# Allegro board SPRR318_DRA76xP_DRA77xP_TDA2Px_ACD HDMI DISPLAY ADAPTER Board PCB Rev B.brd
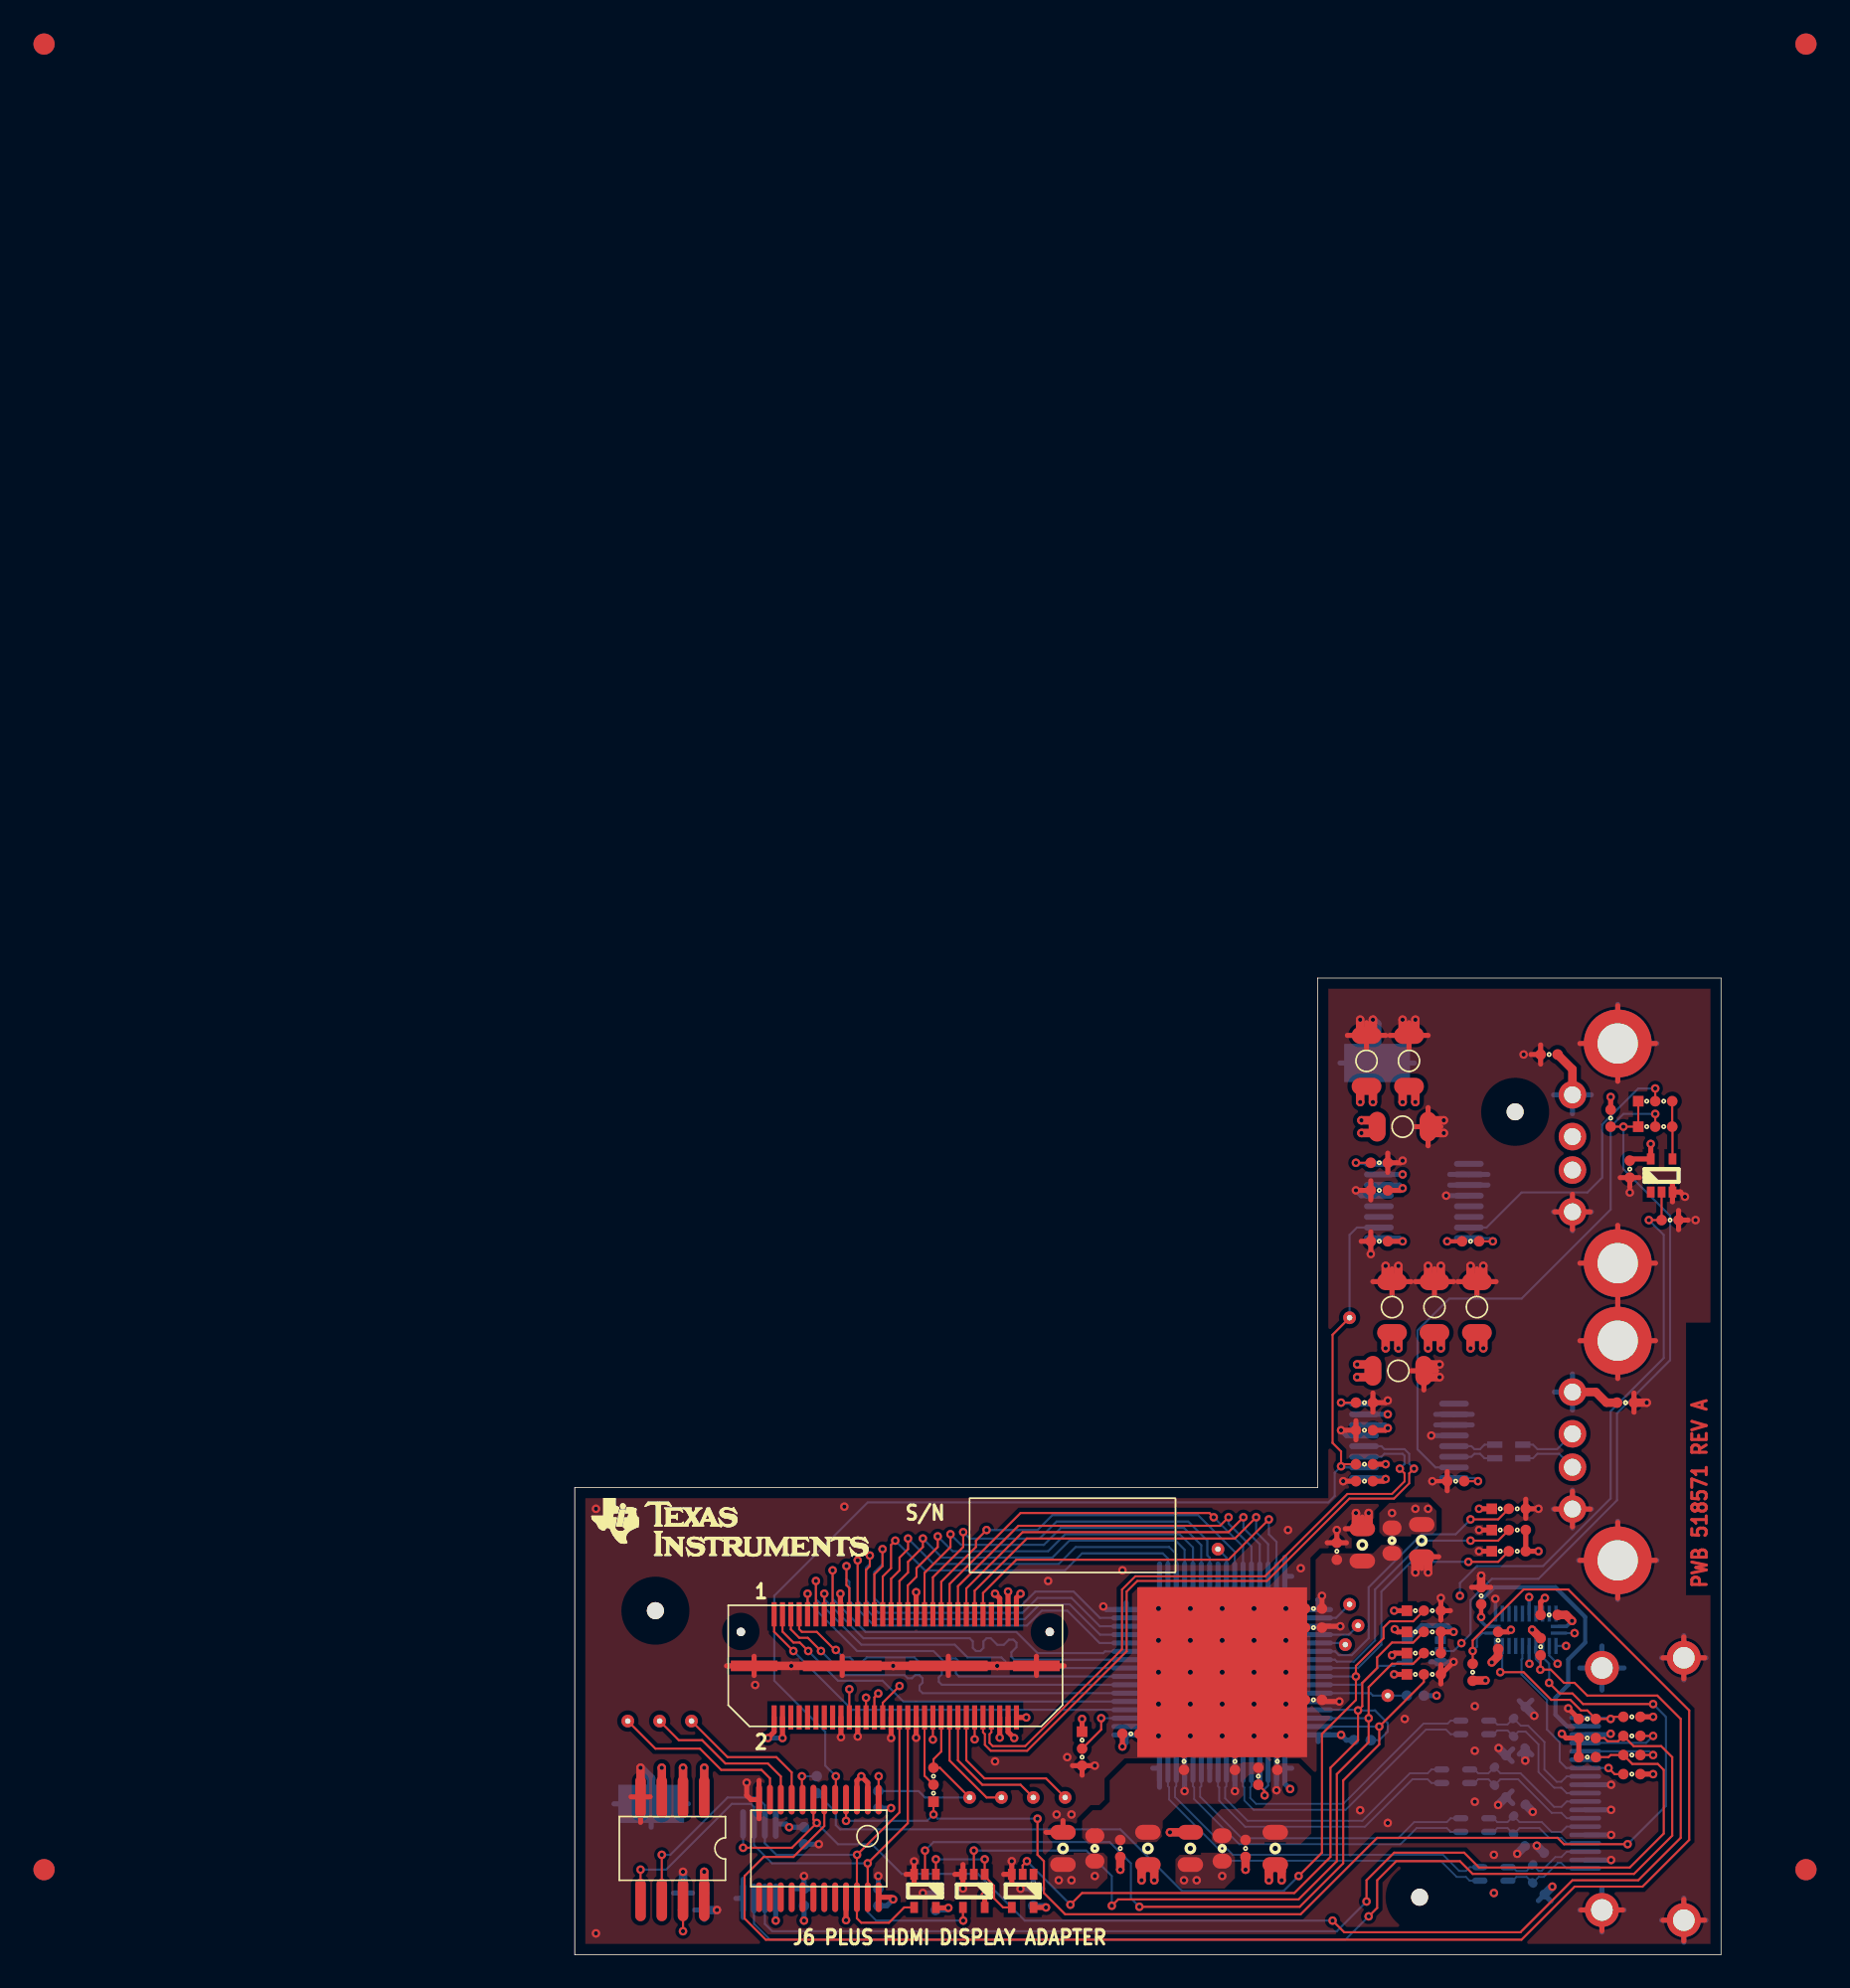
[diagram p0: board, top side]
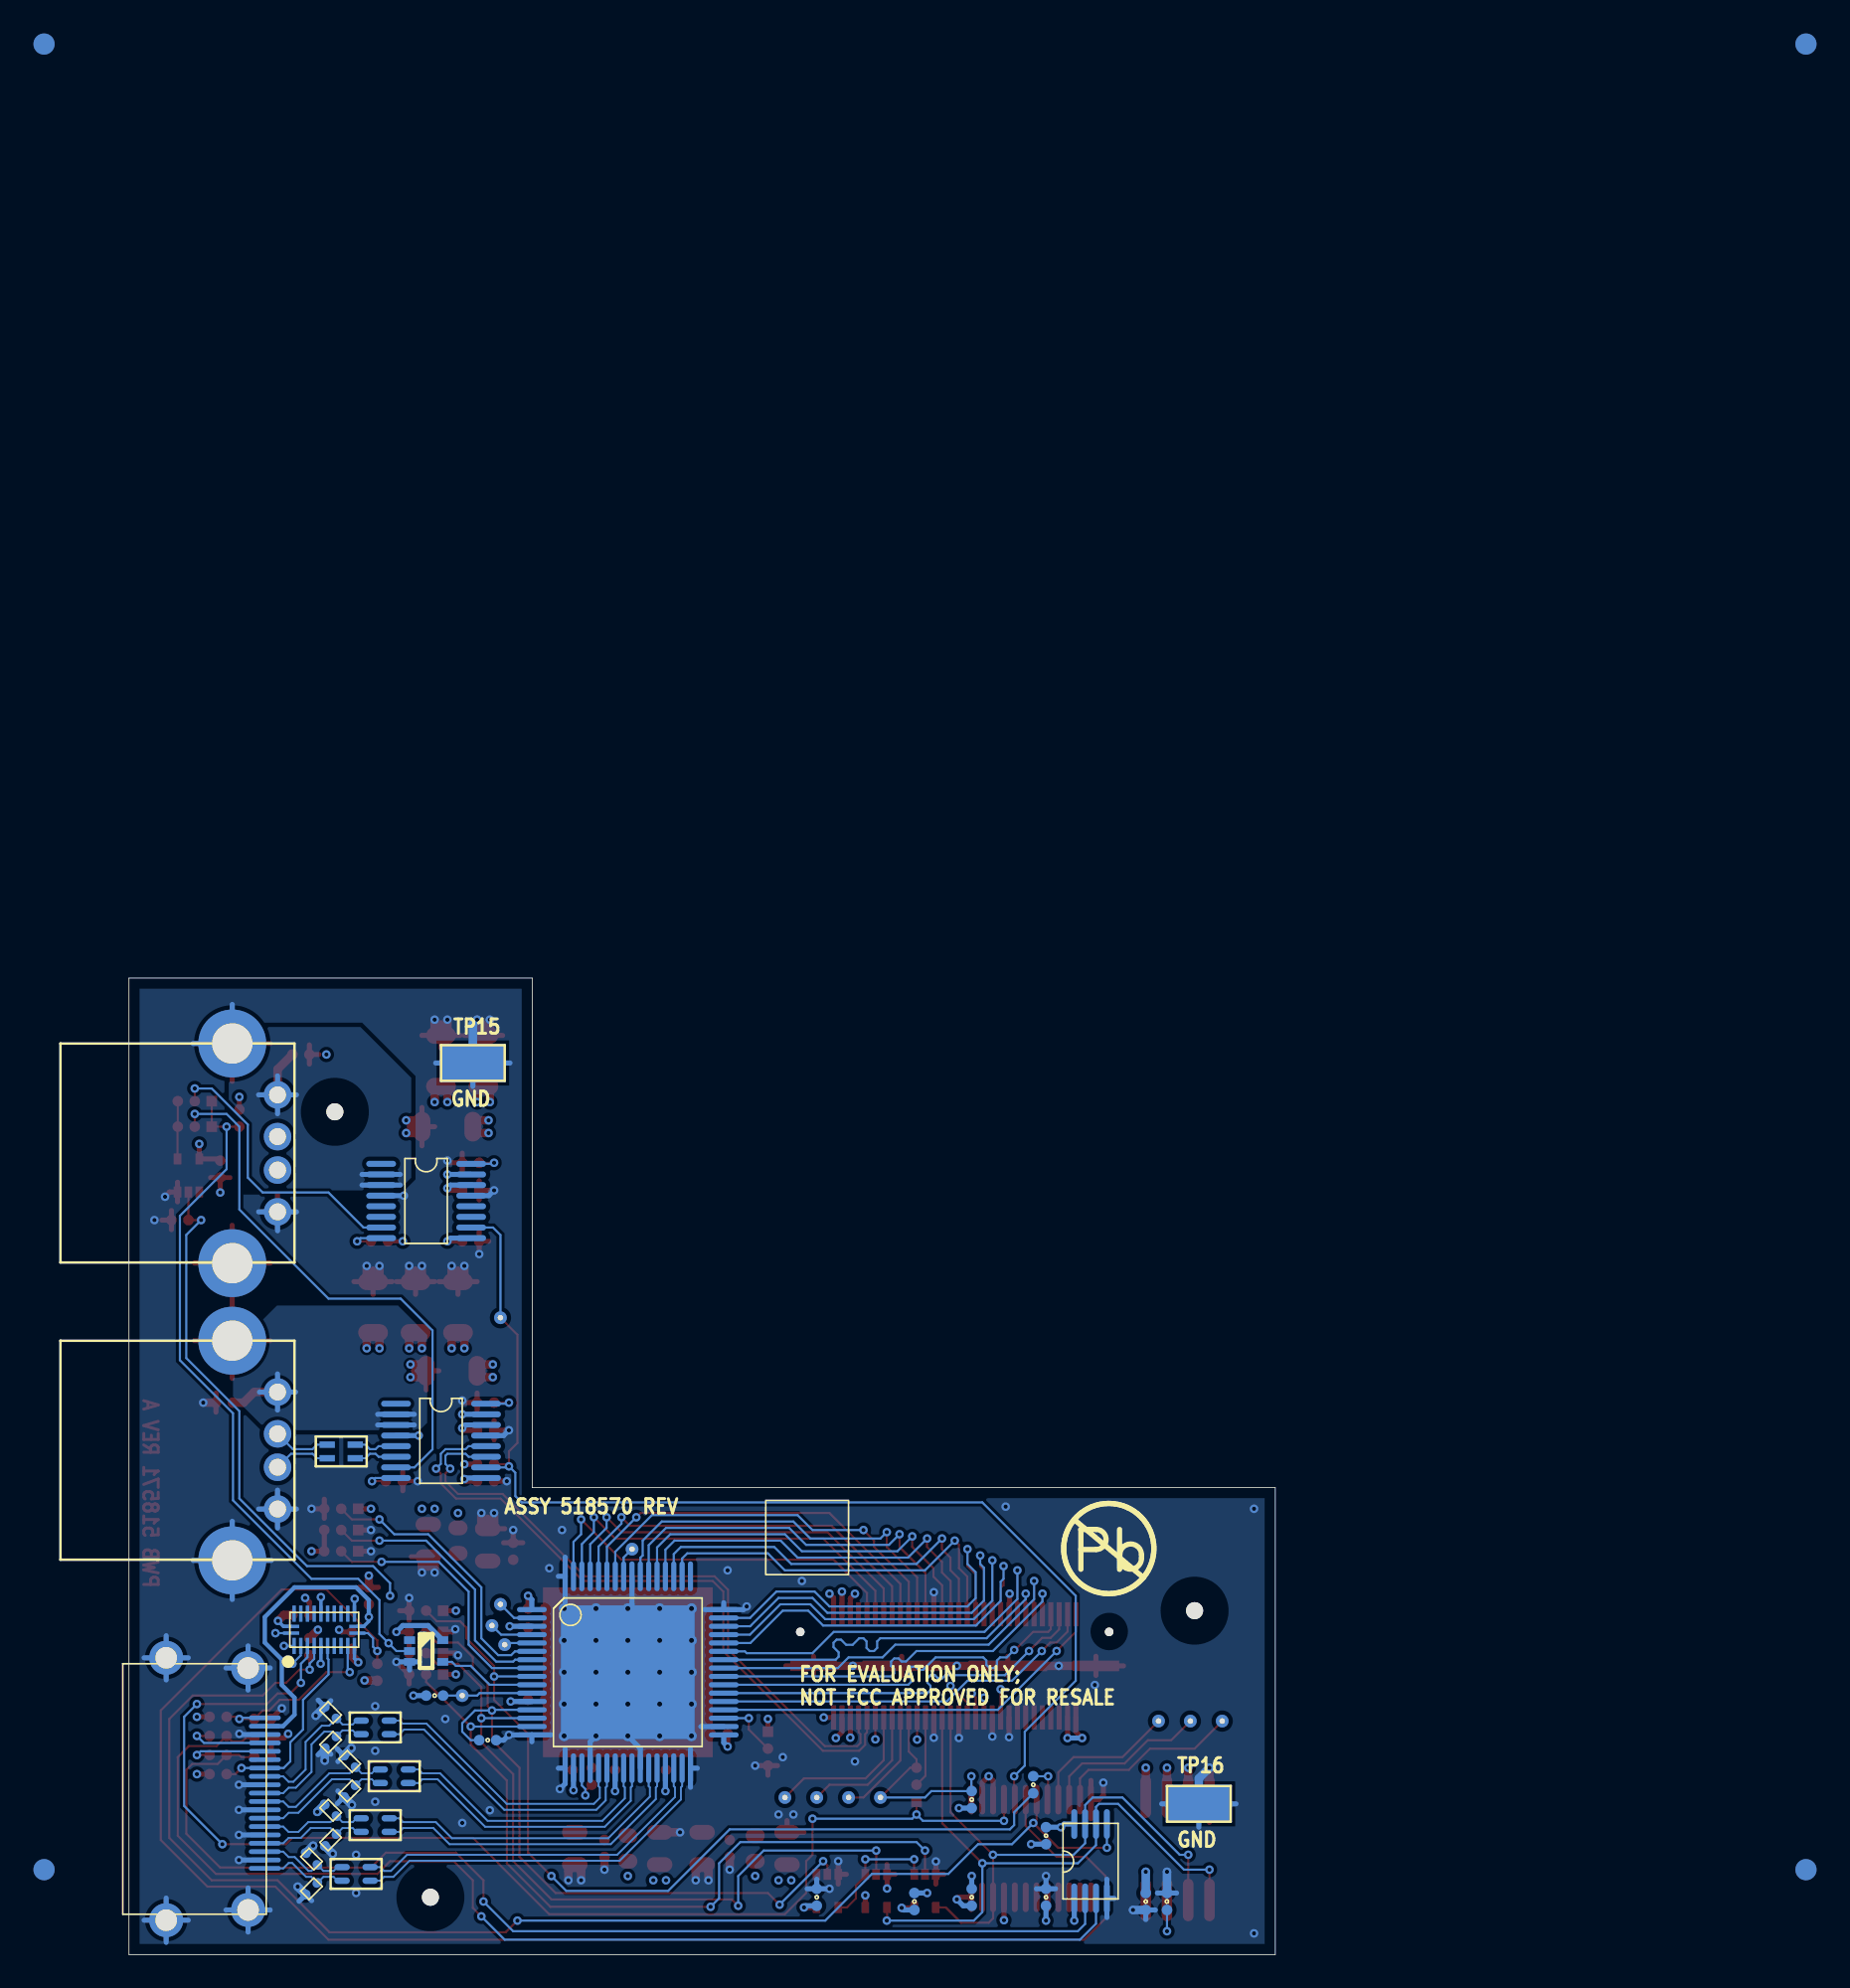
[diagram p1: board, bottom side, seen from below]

Outline 68.58 x 58.42 mm; copper layers: TOP, L2-GND1, L3-SIGNAL, L4-SIGNAL, L5-GND2, BOTTOM. Coordinates in mm from the lower left corner of the outline.
Outline path: 0,27.94 0,0 68.58,0 68.58,58.42 44.45,58.42 44.45,27.94 0,27.94

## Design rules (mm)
net group DP_CON_USB2: nets CONN_USB2_DM CONN_USB2_DP
net group HDMI_CK+: nets HDMI_CK+ TXC+
net group HDMI_CK-: nets HDMI_CK- TXC-
net group HDMI_D0+: nets HDMI_D0+ TX0+
net group HDMI_D0-: nets HDMI_D0- TX0-
net group HDMI_D1+: nets HDMI_D1+ TX1+
net group HDMI_D1-: nets HDMI_D1- TX1-
net group HDMI_D2+: nets HDMI_D2+ TX2+
net group HDMI_D2-: nets HDMI_D2- TX2-
net group 90-OHM: nets USB2_VD+ USB2_VD- USB_DM_DN2 USB_DP_DN2
net group LCD: nets LCD_B0 LCD_B1 LCD_B2 LCD_B3 LCD_B4 LCD_B5 LCD_B6 LCD_B7 LCD_G0 LCD_G1 LCD_G2 LCD_G3 LCD_G4 LCD_G5 LCD_G6 LCD_G7 LCD_R0 LCD_R1 LCD_R2 LCD_R3 LCD_R4 LCD_R5 LCD_R6 LCD_R7
net group PWR: nets VIO_1V8
net group SYNC: nets LCD_DE LCD_HS LCD_PCLK LCD_VS

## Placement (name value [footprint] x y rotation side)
C1  10uF  [C1206-40X70]  47.37 53.47 90 top
C2  10uF  [C1206-40X70]  49.91 53.47 90 top
C3  0.1uF  [C402-25]  58.29 53.85 180 top
C4  10uF  [C1206-40X70]  49.53 49.53 0 top
C5  0.1uF  [C402-25]  48.13 45.72 180 top
C6  1uF  [C402-25]  48.13 42.67 180 top
C7  10uF  [C1206-40X70]  48.9 38.73 90 top
C8  10uF  [C1206-40X70]  51.44 38.73 90 top
C9  10uF  [C1206-40X70]  53.98 38.73 90 top
C10  10uF  [C1206-40X70]  49.28 34.92 0 top
C11  0.1uF  [C402-25]  62.87 33.02 0 top
C12  0.1uF  [C402-25]  47.24 31.37 180 top
C13  1uF  [C402-25]  47.24 28.32 180 top
C14  10uF  [C805-35X60]  50.67 24.77 270 top
C15  0.1uF  [C402-25]  45.59 24.13 90 top
C16  10uF  [C805-35X60]  47.12 24.51 90 top
C17  0.01uF  [C402-25]  44.2 20.7 180 top
C18  0.01uF  [C402-25]  44.2 19.56 180 top
C19  0.1uF  [C402-25]  44.2 15.24 180 top
C20  0.1uF  [C402-25]  33.27 13.21 0 top
C21  0.1uF  [C402-25]  36.45 11.56 90 top
C22  0.01uF  [C402-25]  39.5 11.56 90 top
C23  0.01uF  [C402-25]  42.04 11.56 90 top
C24  0.1uF  [C402-25]  32.64 6.35 270 top
C25  0.1uF  [C402-25]  40.13 6.35 270 top
C26  10uF  [C805-35X60]  34.29 6.35 270 top
C27  10uF  [C805-35X60]  41.91 6.35 270 top
C28  10uF  [C805-35X60]  29.21 6.35 90 top
C29  10uF  [C805-35X60]  36.83 6.35 90 top
C30  0.1uF  [C402-25]  27.43 3.43 90 bottom
C31  0.1uF  [C402-25]  54.23 21.46 90 top
C32  0.1uF  [C402-25]  55.24 18.8 90 top
C33  0.1uF  [C402-25]  21.59 3.17 90 bottom
C34  0.1uF  [C402-25]  7.75 3.17 90 bottom
C35  0.1uF  [C402-25]  58.29 20.32 180 top
C36  0.1uF  [C402-25]  18.16 3.43 90 bottom
C37  NP-1uF  [C402-25]  47.12 12.83 180 bottom
C38  0.1uF  [C402-25]  63.12 46.99 90 top
C39  0.1uF  [C402-25]  13.72 7.11 270 bottom
C40  0.1uF  [C402-25]  13.72 3.43 90 bottom
FL1  DLW21SN121HQ2  [EMI-36X15-DLW21]  55.88 30.1 0 bottom
FL2  DLW21SN900HQ2  [EMI-36X15-DLW21-RDPADS]  54.99 4.83 0 bottom
FL3  DLW21SN900HQ2  [EMI-36X15-DLW21-RDPADS]  53.85 7.75 0 bottom
FL4  DLW21SN900HQ2  [EMI-36X15-DLW21-RDPADS]  52.7 10.67 0 bottom
FL5  DLW21SN900HQ2  [EMI-36X15-DLW21-RDPADS]  53.85 13.59 0 bottom
J1  QTH-030-02-L-D-A  [QTH30-12X57]  19.18 17.27 0 top
L1  BLM18AG601SN1D  [L603-35X45]  48.9 24.77 270 top
L2  BLM18AG601SN1D  [L603-35X45]  38.73 6.35 90 top
L3  BLM18AG601SN1D  [L603-35X45]  31.11 6.35 90 top
NOREF  -  []  0.13 23.62 0 top
NOREF#2  -  []  -36.83 119.38 0 top
NOREF#3  -  []  68.58 0 0 top
NOREF#4  -  [unnamed#2]  73.66 5.08 0 top
NOREF#5  -  []  68.58 117.43 0 top
NOREF#6  -  [unnamed#2]  -31.75 5.08 0 top
NOREF#7  -  [unnamed#2]  73.66 114.3 0 top
NOREF#8  -  []  68.58 0 90 top
NOREF#9  -  []  78.74 0 90 top
NOREF#10  -  []  -403.99 -204.01 0 top
NOREF#11  -  []  -403.99 -204.01 0 top
NOREF#12  -  [unnamed#2]  -31.75 114.3 0 top
NOREF#13  -  []  -26.67 119.38 0 top
NOREF#14  -  []  0 0 0 top
NOREF#15  -  []  68.58 58.42 90 top
NOREF#16  -  [unnamed#3]  4.83 20.57 0 bottom
NOREF#17  -  [unnamed#3]  56.26 50.42 0 bottom
NOREF#18  -  [unnamed#2]  -31.75 114.3 180 bottom
NOREF#19  -  []  13.34 20.83 180 bottom
NOREF#20  -  [unnamed#3]  50.55 3.43 0 bottom
NOREF#21  -  [unnamed#2]  73.66 114.3 180 bottom
NOREF#22  -  [unnamed#2]  73.66 5.08 180 bottom
NOREF#23  -  [unnamed#2]  -31.75 5.08 180 bottom
P1  USB-A connector  [USB_A_SH]  59.69 51.44 270 bottom
P2  USB-A connector  [USB_A_SH]  59.69 33.66 270 bottom
P3  HDMI-RA-19-TYPEA  [HDMI-SMT-W-FLANGE-RDPADS]  60.45 9.91 270 bottom
R1  100K  [R402-25]  48.13 47.37 0 top
R2  100K  [R402-25]  61.98 50.04 270 top
R3  10K  [R402-25]  53.59 42.67 180 top
R4  100K  [R402-25]  47.24 33.02 0 top
R5  10K  [R402-25]  47.24 29.34 180 top
R6  10K  [R402-25]  52.7 28.32 0 top
R7  NP  [R402-25]  63.25 14.22 0 top
R8  10K  [R402-25]  60.58 14.1 180 top
R9  10K  [R402-25]  60.58 12.95 180 top
R10  10K  [R402-25]  60.58 11.81 180 top
R11  NP  [R402-25]  63.25 10.79 0 top
R12  10K  [R402-25]  50.29 15.49 180 bottom
R13  10K  [R402-25]  53.72 16.89 90 top
R14  10K  [R402-25]  18.16 9.27 90 bottom
R15  2K  [R402-25]  6.48 3.17 90 bottom
R16  510  [R402-25]  40.89 10.67 270 top
R17  NP  [R402-25]  14.48 10.16 270 bottom
R18  10K  [R402-25]  57.78 18.41 270 top
R19  10K  [R402-25]  65.53 43.94 0 top
R20  22.1  [R402-25]  63.25 11.94 0 top
R21  22.1  [R402-25]  63.25 13.08 0 top
RJ1  10K.A  [JMP402-25]  55.37 26.67 0 top
RJ2  10K.A  [JMP402-25]  55.37 25.4 0 top
RJ3  10K.A  [JMP402-25]  55.37 24.13 0 top
RJ4  10K.A  [JMP402-25]  50.29 20.57 0 top
RJ5  10K.A  [JMP402-25]  50.29 19.3 0 top
RJ6  10K.A  [JMP402-25]  50.29 18.03 0 top
RJ7  10K.A  [JMP402-25]  50.29 16.76 0 top
RJ8  10K.A  [JMP402-25]  30.35 12.83 270 top
RJ9  0.A  [JMP402-25]  21.46 9.65 90 top
RJ10  0.A  [JMP402-25]  64.14 51.05 0 top
RJ11  0.A  [JMP402-25]  64.14 49.53 0 top
TP1  RD30  [TP-30RD13]  46.35 38.1 0 top
TP2  RD30  [TP-30RD13]  38.48 24.26 0 top
TP3  RD30  [TP-30RD13]  46.1 18.54 0 top
TP4  RD30  [TP-30RD13]  46.86 19.68 0 top
TP5  RD30  [TP-30RD13]  46.35 20.95 0 top
TP6  RD30  [TP-30RD13]  48.64 15.49 180 top
TP7  RD30  [TP-30RD13]  3.17 13.97 0 top
TP8  RD30  [TP-30RD13]  5.08 13.97 0 top
TP9  RD30  [TP-30RD13]  6.99 13.97 0 top
TP10  RD30  [TP-30RD13]  23.62 9.4 0 top
TP11  RD30  [TP-30RD13]  25.53 9.4 0 top
TP12  RD30  [TP-30RD13]  27.43 9.4 0 top
TP13  RD30  [TP-30RD13]  29.34 9.4 0 top
TP15  TPSLP  [TP1-70X135]  48.01 53.34 90 bottom
TP16  TPSLP  [TP1-70X135]  4.57 9.02 90 bottom
U1  SN74LVC1G04DCK  [DCK-5]  50.8 18.16 270 bottom
U2  74CBTLV1G125CRG4  [DCK-5]  23.88 3.81 180 top
U3  SN74LVC1G04DCK  [DCK-5]  26.8 3.81 180 top
U4  74CBTLV1G125CRG4  [DCK-5]  20.95 3.81 180 top
U5  24WC256  [SO8-25X75-295]  5.84 6.35 180 top
U6  PCF8575  [PW24-14X70]  14.61 6.35 180 top
U7  TPD3S716-Q1  [SSOP-16]  50.8 45.09 270 bottom
U8  TPD3S716-Q1  [SSOP-16]  49.91 30.73 270 bottom
U9  TFP410(EP)  [PAP64-12X70]  38.73 16.89 270 bottom
U10  TPD12S016RKTR  [RKT24]  56.9 19.43 180 bottom
U11  tpd1e05u06  [DPY-RDPADS]  57.66 3.94 315 bottom
U12  tpd1e05u06  [DPY-RDPADS]  57.66 5.71 45 bottom
U13  tpd1e05u06  [DPY-RDPADS]  56.52 6.86 315 bottom
U14  tpd1e05u06  [DPY-RDPADS]  56.52 8.64 45 bottom
U15  tpd1e05u06  [DPY-RDPADS]  55.37 9.78 315 bottom
U16  tpd1e05u06  [DPY-RDPADS]  55.37 11.56 45 bottom
U17  tpd1e05u06  [DPY-RDPADS]  56.52 12.7 315 bottom
U18  tpd1e05u06  [DPY-RDPADS]  56.52 14.48 45 bottom
U19  SN74LVC1G04DCK  [DCK-5]  65.02 46.61 0 top
U20  PCA9507DP  [DGK8-14X70]  11.05 5.59 180 bottom

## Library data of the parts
C1 C2 C4 C7-C10 = CAP: Tolerance: X; User Part Number: X
C3 C5 C11 = Cap 100nF Cermc 16V 10% 603_4: Tolerance: TOLERANCE; User Part Number: USERPART#
C6 C37 = CAP NP_0: Tolerance: TOLERANCE; User Part Number: USERPART#
C12 = Cap 100nF Cermc 16V 10% 603_4: User Part Number: USERPART#; Tolerance: TOLERANCE
C13 = CAP NP_0: User Part Number: USERPART#; Tolerance: TOLERANCE
C14 C16 C26-C29 = CAP_AM_0805_10uf_x7r_10v_10_2: Tolerance: X; User Part Number: X
C15 C19-C21 C24 C25 = 0402_0r1uf_x7r_10v_10: Tolerance: TOLERANCE; User Part Number: USERPART#
C17 C18 C22 C23 C36 C39 = CAP: Tolerance: TOLERANCE; User Part Number: USERPART#
C30-C33 C35 C38 C40 = CAP NP: Tolerance: TOLERANCE; User Part Number: USERPART#
C34 = CAP .1 uF 10% 0603: Tolerance: TOLERANCE; User Part Number: USERPART#
FL1 = DLW21SN121HQ2: User Part Number: PART#; Tolerance: TOL
FL2-FL5 = DLW21SN900HQ2: User Part Number: PART#; Tolerance: TOL; signal model: DLW21SN900HQ2_EMI-36X15-DLW21-R_DLW21SN900HQ2
J1 = QSH-030: User Part Number: PART#; Tolerance: TOL
L1-L3 = 0603_300_100mhz_cb_230ma_25: Tolerance: 25%; User Part Number: X; tolerance: 25%
P1 P2 = USB-A connector: User Part Number: PART#; Tolerance: TOL
P3 = HDMI-RA-19_0: Tolerance: TOL; User Part Number: PART#
R1-R3 R6-R13 R17-R21 = R: Tolerance: TOLERANCE; User Part Number: USERPART#
R4 R5 = R: User Part Number: USERPART#; Tolerance: TOLERANCE
R14 R15 = RESISTOR: Tolerance: TOLERANCE; User Part Number: USERPART#
R16 = RES_0: Tolerance: TOLERANCE; User Part Number: USERPART#
RJ1-RJ11 = RJUMP3: Tolerance: TOLERANCE; User Part Number: USERPART#
TP1 = TP-30RD13: Tolerance: TOLERANCE; User Part Number: USERPART#
TP2-TP13 = TESTPOINT: Tolerance: TOLERANCE; User Part Number: USERPART#
TP15 TP16 = SMT-TP
U1 U3 U19 = SN74LVC1GU04_0: Tolerance: TOL; User Part Number: PART#
U2 U4 = SN74LVC1G125_0: Tolerance: TOL; User Part Number: PART#
U5 = 24WC256: User Part Number: X; Tolerance: X
U6 = PCF8575_1: Tolerance: X; User Part Number: X
U7 U8 = TPD3S716-Q1: User Part Number: USERPART#; Tolerance: TOLERANCE
U9 = TFP410-EP
U10 = TPD12S016RKTR_QFN24_3: Tolerance: X; User Part Number: X
U11-U18 = tpd1e05u06: Tolerance: X; User Part Number: X
U20 = PCA9507DP: User Part Number: X; Tolerance: X

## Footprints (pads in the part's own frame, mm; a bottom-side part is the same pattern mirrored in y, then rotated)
C402-25
  round 0.635 smd: 1(-0.508,0) 2(0.508,0)
C805-35X60
  oval 0.889x1.524 smd: 1(-0.965,0) 2(0.965,0)
C1206-40X70
  oval 1.016x1.778 smd: 1(-1.524,0) 2(1.524,0)
DCK-5
  rect 0.46x0.66 smd: 1(-0.65,-0.991) 2(0,-0.991) 3(0.65,-0.991) 4(0.65,0.991) 5(-0.65,0.991)
DGK8-14X70
  oval 0.356x1.778 smd: 1(-0.975,-2.225) 2(-0.325,-2.225) 3(0.325,-2.225) 4(0.975,-2.225) 5(0.975,2.223) 6(0.325,2.223) 7(-0.325,2.223) 8(-0.975,2.223)
DPY-RDPADS
  oval 0.61x0.508 smd: 1(-0.495,0) 2(0.495,0)
EMI-36X15-DLW21
  rect 0.914x0.381 smd: 1(-0.838,0.406) 2(0.838,0.406) 3(0.838,-0.406) 4(-0.838,-0.406)
EMI-36X15-DLW21-RDPADS
  oval 0.914x0.381 smd: 1(-0.838,0.406) 2(0.838,0.406) 3(0.838,-0.406) 4(-0.838,-0.406)
HDMI-SMT-W-FLANGE-RDPADS
  oval 0.279x1.905 smd: 1(4.75,0) 2(4.249,0) 3(3.749,0) 4(3.249,0) 5(2.748,0) 6(2.248,0) 7(1.748,0) 8(1.247,0) 9(0.747,0) 10(0.246,0) 11(-0.254,0) 12(-0.754,0) 13(-1.255,0) 14(-1.755,0) 15(-2.256,0) 16(-2.756,0) 17(-3.256,0) 18(-3.757,0) 19(-4.257,0)
  round 2.032 hole 1.295: MTG1(-7.239,-1.001) MTG2(7.239,-1.001) MTG3(-7.849,-5.9) MTG4(7.849,-5.9)
JMP402-25
  rect 0.635x0.635 smd: 1(-0.508,0)
  round 0.635 smd: 2(0.508,0) 3(1.524,0)
L603-35X45
  oval 0.889x1.143 smd: 1(-0.762,0) 2(0.762,0)
PAP64-12X70
  oval 0.305x1.778 smd: 1(-3.749,-5.74) 2(-3.249,-5.74) 3(-2.749,-5.74) 4(-2.249,-5.74) 5(-1.75,-5.74) 6(-1.25,-5.74) 7(-0.75,-5.74) 8(-0.25,-5.74) 9(0.25,-5.74) 10(0.75,-5.74) 11(1.25,-5.74) 12(1.75,-5.74) 13(2.249,-5.74) 14(2.749,-5.74) 15(3.249,-5.74) 16(3.749,-5.74) 33(3.749,5.74) 34(3.249,5.74) 35(2.749,5.74) 36(2.249,5.74) 37(1.75,5.74) 38(1.25,5.74) 39(0.75,5.74) 40(0.25,5.74) 41(-0.25,5.74) 42(-0.75,5.74) 43(-1.25,5.74) 44(-1.75,5.74) 45(-2.249,5.74) 46(-2.749,5.74) 47(-3.249,5.74) 48(-3.749,5.74)
  oval 1.778x0.305 smd: 17(5.74,-3.749) 18(5.74,-3.249) 19(5.74,-2.749) 20(5.74,-2.249) 21(5.74,-1.75) 22(5.74,-1.25) 23(5.74,-0.75) 24(5.74,-0.25) 25(5.74,0.25) 26(5.74,0.75) 27(5.74,1.25) 28(5.74,1.75) 29(5.74,2.249) 30(5.74,2.749) 31(5.74,3.249) 32(5.74,3.749) 49(-5.74,3.749) 50(-5.74,3.249) 51(-5.74,2.749) 52(-5.74,2.249) 53(-5.74,1.75) 54(-5.74,1.25) 55(-5.74,0.75) 56(-5.74,0.25) 57(-5.74,-0.25) 58(-5.74,-0.75) 59(-5.74,-1.25) 60(-5.74,-1.75) 61(-5.74,-2.249) 62(-5.74,-2.749) 63(-5.74,-3.249) 64(-5.74,-3.749)
  rect 8.001x8.001 smd: 65(0,0)
PW24-14X70
  oval 0.356x1.778 smd: 1(-3.576,-2.921) 2(-2.926,-2.921) 3(-2.276,-2.921) 4(-1.626,-2.921) 5(-0.975,-2.921) 6(-0.325,-2.921) 7(0.325,-2.921) 8(0.975,-2.921) 9(1.626,-2.921) 10(2.276,-2.921) 11(2.926,-2.921) 12(3.576,-2.921) 13(3.576,2.921) 14(2.926,2.921) 15(2.276,2.921) 16(1.626,2.921) 17(0.975,2.921) 18(0.325,2.921) 19(-0.325,2.921) 20(-0.975,2.921) 21(-1.626,2.921) 22(-2.276,2.921) 23(-2.926,2.921) 24(-3.576,2.921)
QTH30-12X57
  round 0.508 hole 1.016 unplated: (-9.237,2.032) (9.241,2.032)
  rect 0.305x1.448 smd: 1(-7.248,3.086) 2(-7.248,-3.086) 3(-6.748,3.086) 4(-6.748,-3.086) 5(-6.248,3.086) 6(-6.248,-3.086) 7(-5.749,3.086) 8(-5.749,-3.086) 9(-5.249,3.086) 10(-5.249,-3.086) 11(-4.749,3.086) 12(-4.749,-3.086) 13(-4.249,3.086) 14(-4.249,-3.086) 15(-3.749,3.086) 16(-3.749,-3.086) 17(-3.249,3.086) 18(-3.249,-3.086) 19(-2.749,3.086) 20(-2.749,-3.086) 21(-2.249,3.086) 22(-2.249,-3.086) 23(-1.75,3.086) 24(-1.75,-3.086) 25(-1.25,3.086) 26(-1.25,-3.086) 27(-0.75,3.086) 28(-0.75,-3.086) 29(-0.25,3.086) 30(-0.25,-3.086) 31(0.25,3.086) 32(0.25,-3.086) 33(0.75,3.086) 34(0.75,-3.086) 35(1.25,3.086) 36(1.25,-3.086) 37(1.75,3.086) 38(1.75,-3.086) 39(2.249,3.086) 40(2.249,-3.086) 41(2.749,3.086) 42(2.749,-3.086) 43(3.249,3.086) 44(3.249,-3.086) 45(3.749,3.086) 46(3.749,-3.086) 47(4.249,3.086) 48(4.249,-3.086) 49(4.749,3.086) 50(4.749,-3.086) 51(5.249,3.086) 52(5.249,-3.086) 53(5.749,3.086) 54(5.749,-3.086) 55(6.248,3.086) 56(6.248,-3.086) 57(6.748,3.086) 58(6.748,-3.086) 59(7.248,3.086) 60(7.248,-3.086)
  rect 2.794x0.635 smd: 61(-8.445,0) 64(8.445,0)
  rect 4.699x0.635 smd: 62(-3.175,0) 63(3.175,0)
R402-25
  round 0.635 smd: 1(-0.508,0) 2(0.508,0)
RKT24
  rect 0.203x0.965 smd: 1(-1.806,-0.965) 2(-1.405,-0.965) 3(-1.003,-0.965) 4(-0.602,-0.965) 5(-0.201,-0.965) 6(0.201,-0.965) 7(0.602,-0.965) 8(1.003,-0.965) 9(1.405,-0.965) 10(1.806,-0.965) 13(1.806,0.965) 14(1.405,0.965) 15(1.003,0.965) 16(0.602,0.965) 17(0.201,0.965) 18(-0.201,0.965) 19(-0.602,0.965) 20(-1.003,0.965) 21(-1.405,0.965) 22(-1.806,0.965)
  rect 0.965x0.203 smd: 11(1.981,-0.201) 12(1.981,0.201) 23(-1.981,0.201) 24(-1.981,-0.201)
SO8-25X75-295
  oval 0.635x2.54 smd: 1(-1.905,-3.086) 2(-0.635,-3.086) 3(0.635,-3.086) 4(1.905,-3.086) 5(1.905,3.086) 6(0.635,3.086) 7(-0.635,3.086) 8(-1.905,3.086)
SSOP-16
  oval 0.356x1.778 smd: 1(-2.223,-2.692) 2(-1.587,-2.692) 3(-0.953,-2.692) 4(-0.318,-2.692) 5(0.318,-2.692) 6(0.953,-2.692) 7(1.587,-2.692) 8(2.223,-2.692) 9(2.223,2.692) 10(1.587,2.692) 11(0.953,2.692) 12(0.318,2.692) 13(-0.318,2.692) 14(-0.953,2.692) 15(-1.587,2.692) 16(-2.223,2.692)
TP1-70X135
  rect 2.286x3.937 smd: 1(0,0)
TP-30RD13
  round 0.762 hole 0.33: 1(0,0)
unnamed#2
  round 1.27 smd: 1(0,0)
unnamed#3
  round 1.016 hole 2.362 unplated: (0,0)
USB_A_SH
  round 1.651 hole 1.016: 1(0,0) 2(2.499,0) 3(4.501,0) 4(7,0)
  round 4.064 hole 2.413: 5(-3.071,-2.71) 6(10.071,-2.71)

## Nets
GND: C1.2 C2.2 C3.2 C4.2 C5.2 C6.2 C7.2 C8.2 C9.2 C10.2 C11.2 C12.2 C13.2 C14.2 C15.2 C16.2 C17.2 C18.2 C19.2 C20.2 C21.2 C22.2 C23.2 C24.2 C25.2 C26.2 C27.2 C28.2 C29.2 C30.2 C31.2 C32.2 C33.2 C34.1 C35.2 C36.2 C37.2 C38.1 C39.2 C40.2 J1.17 J1.18 J1.22 J1.30 J1.35 J1.36 J1.61(GNDCT1) J1.62(GNDCT2) J1.63(GNDCT3) J1.64(GNDCT4) P1.4(GND) P1.5(S2) P1.6(S1) P2.4(GND) P2.5(S2) P2.6(S1) P3.2(D2 SHIELD) P3.5(D1 SHIELD) P3.8(D0 SHIELD) P3.11(CK SHIELD) P3.17(GND) P3.MTG1 P3.MTG2 P3.MTG3 P3.MTG4 R1.2 R4.2 R6.1 R8.2 R15.2 R19.2 RJ1.3 RJ2.1 RJ3.1 RJ4.3 RJ5.1 RJ6.1 RJ7.3 RJ8.3 TP15.1 TP16.1 U1.3(GND) U2.3(GND) U3.3(GND) U4.3(GND) U5.4(VSS) U6.12(GND) U7.4(GND#4) U7.13(GND#13) U8.4(GND#4) U8.13(GND#13) U9.16(DGND#16) U9.17(PGND) U9.20(TGND#20) U9.26(TGND#26) U9.32(TGND#32) U9.34(RSV34) U9.48(DGND#48) U9.56(IDCK-) U9.64(DGND#64) U9.65(PWR_PAD) U10.5(GND1) U10.13(GND2) U10.18(GND3) U11.2(GND) U12.2(GND) U13.2(GND) U14.2(GND) U15.2(GND) U16.2(GND) U17.2(GND) U18.2(GND) U19.3(GND) U20.4(GND)
VBUS2: C11.1 P2.1(VBUS) U8.2(VBUS_CON#2) U8.3(VBUS_CON#3)
VBUS_AUX: C3.1 P1.1(VBUS) U7.2(VBUS_CON#2) U7.3(VBUS_CON#3)
A3/DK3: RJ1.2 U9.6(A3/DK3)
BSEL/SCL: RJ7.2 U4.2(I) U9.15(BSEL/SCL)
CLT2/A1/DK2: RJ2.2 U9.7(CLT2/A1/DK2)
CON_LCD_PWR_DN: J1.40 R2.2 RJ10.1 RJ11.1 U1.2(I)
CONN_USB2_DM: FL1.3 P2.2(D-)
CONN_USB2_DP: FL1.2 P2.3(D+)
CT_HPD: R13.2 U6.6(P2) U10.11(CT_HPD)
CTL1/A1/DK1: RJ3.2 U9.8(CTL1/A1/DK1)
DISP_SCL: J1.32 U4.4(O) U5.6(SCL) U6.22(SCL) U20.7(SCLB)
DISP_SDA: J1.34 U2.4(O) U5.5(SDA) U6.23(SDA) U20.6(SDAB)
DKEN: RJ8.2 U9.35(DKEN)
DSEL/SDA: RJ6.2 U2.2(I) U9.14(DSEL/SDA)
EDGE/HTPLG: R17.2 RJ4.2 U9.9(EDGE/HTPLG)
GP1[2]_TOUCH_EVT: J1.38 RJ9.2
HDMI_5V: C31.1 P3.18(+5V) U10.12(5V_OUT)
HDMI_CEC: P3.13(CE REMOTE) R11.1 U10.6(CEC_B)
HDMI_CK+: FL5.2 P3.10(CK+) U17.1(IO)
HDMI_CK-: FL5.3 P3.12(CK-) U18.1(IO)
HDMI_D0+: FL4.2 P3.7(D0+) U15.1(IO)
HDMI_D0-: FL4.3 P3.9(D0-) U16.1(IO)
HDMI_D1+: FL3.2 P3.4(D1+) U13.1(IO)
HDMI_D1-: FL3.3 P3.6(D1-) U14.1(IO)
HDMI_D2+: FL2.2 P3.1(D2+) U11.1(IO)
HDMI_D2-: FL2.3 P3.3(D2-) U12.1(IO)
HDMI_DPD: P3.19(HP DET) R7.1 R8.1 U10.9(HPD_B)
HDMI_SCL: P3.15(DDC CLK) R20.2
HDMI_SDA: P3.16(DDC DATA) R21.2
HPD_A: RJ9.1 U6.4(P0) U10.3(HPD_A)
ISEL/RSTN: C37.1 RJ5.2 U3.2(I) U9.13(ISEL/RSTN)
ISELN: U2.1(OE) U3.4(O) U4.1(OE)
LCD_B0: J1.51 U9.63(D0)
LCD_B1: J1.49 U9.62(D1)
LCD_B2: J1.47 U9.61(D2)
LCD_B3: J1.45 U9.60(D3)
LCD_B4: J1.43 U9.59(D4)
LCD_B5: J1.41 U9.58(D5)
LCD_B6: J1.39 U9.55(D6)
LCD_B7: J1.37 U9.54(D7)
LCD_DE: J1.28 TP5.1(TP) U9.2(DE)
LCD_G0: J1.33 U9.53(D8)
LCD_G1: J1.31 U9.52(D9)
LCD_G2: J1.29 U9.51(D10)
LCD_G3: J1.27 U9.50(D11)
LCD_G4: J1.25 U9.47(D12)
LCD_G5: J1.23 U9.46(D13)
LCD_G6: J1.21 U9.45(D14)
LCD_G7: J1.19 U9.44(D15)
LCD_HS: J1.26 TP4.1(TP) U9.4(HSYNC)
LCD_PCLK: J1.20 TP2.1(TP) U9.57(IDCK+)
LCD_R0: J1.15 U9.43(D16)
LCD_R1: J1.13 U9.42(D17)
LCD_R2: J1.11 U9.41(D18)
LCD_R3: J1.9 U9.40(D19)
LCD_R4: J1.7 U9.39(D20)
LCD_R5: J1.5 U9.38(D21)
LCD_R6: J1.3 U9.37(D22)
LCD_R7: J1.1 U9.36(D23)
LCD_VS: J1.24 TP3.1(TP) U9.5(VSYNC)
LS_OE: R18.2 U6.7(P3) U10.4(LS_OE) U20.5(EN)
PCF8575_OUT5: TP9.1(TP) U6.9(P5)
PCF8575_OUT6: TP8.1(TP) U6.10(P6)
PCF8575_OUT7: TP7.1(TP) U6.11(P7)
PDN: U1.4(O) U9.10(PDN)
TS_LCD_GPIO1: J1.48 TP13.1(TP)
TS_LCD_GPIO2: J1.46 TP12.1(TP)
TS_LCD_GPIO3: J1.44 TP11.1(TP)
TS_LCD_GPIO4: J1.42 R14.2 RJ9.3 TP10.1(TP) U6.1(I\N\T\)
TX0+: FL4.1 U9.25(TX0+)
TX0-: FL4.4 U9.24(TX0-)
TX1+: FL3.1 U9.28(TX1+)
TX1-: FL3.4 U9.27(TX1-)
TX2+: FL2.1 U9.31(TX2+)
TX2-: FL2.4 U9.30(TX2-)
TXC+: FL5.1 U9.22(TXC+)
TXC-: FL5.4 U9.21(TXC-)
USB2_DRV_VBUS: J1.50 R19.1 U19.2(I)
USB2_VBUS_OCN: R5.2 TP1.1(TP) U6.5(P1) U7.10(FLT) U8.10(FLT)
USB2_VD+: FL1.1 U8.6(VD+)
USB2_VD-: FL1.4 U8.5(VD-)
USB_DM_DN2: J1.52 U8.12(D-)
USB_DP_DN2: J1.54 U8.11(D+)
USBP1_PWR_VENN: RJ10.2 U7.7(VEN)
USBP2_PWR_VENN: RJ11.2 U8.7(VEN)
V_DVDD: C15.1 C16.1 C17.1 C18.1 C19.1 C20.1 L1.2(P2) U9.1(DVDD#1) U9.3(VREF) U9.12(DVDD#12) U9.33(DVDD#33)
V_PVDD: C23.1 C25.1 C27.1 L2.2(P2) U9.18(PVDD)
V_TVDD: C21.1 C22.1 C24.1 C26.1 L3.2(P2) R16.1 U9.23(TVDD#23) U9.29(TVDD#29)
VIO_1V8: J1.2 J1.4
VIO_3V3: C6.1 C13.1 C14.1 C28.1 C29.1 C30.1 C33.1 C34.2 C35.1 C36.1 C38.2 C39.1 J1.56 J1.58 J1.60 L1.1(P1) L2.1(P1) L3.1(P1) R2.1 R3.2 R5.1 R11.2 R12.1 R13.1 R14.1 R18.1 RJ1.1 RJ2.3 RJ3.3 RJ4.1 RJ5.3 RJ6.3 RJ7.1 RJ8.1 U1.5(VCC) U2.5(VCC) U3.5(VCC) U4.5(VCC) U5.1(A0) U5.2(A1) U5.3(NC) U5.8(VCC) U6.2(A1) U6.3(A2) U6.21(A0) U6.24(VDD) U7.9(VIN) U8.9(VIN) U10.23(VCCA) U19.5(VCC) U20.8(VCCB)
VSYS_5V0: C1.1 C2.1 C4.1 C5.1 C7.1 C8.1 C9.1 C10.1 C12.1 C32.1 C40.1 J1.55 J1.57 J1.59 R7.2 R9.2 R10.2 U7.14(VBUS_SYS#14) U7.15(VBUS_SYS#15) U8.14(VBUS_SYS#14) U8.15(VBUS_SYS#15) U10.10(VCC5V) U20.1(VCCA)
N22084: R16.2 U9.19(TFADJ)
N30894: R12.2 TP6.1(TP) U9.11(MSEN/PO1)
N46927: R15.1 U5.7(WP)
N16782581: R4.1 U8.16(IADJ)
N16782836: R6.2 U8.8(DEN)
N16782935: R1.1 U7.16(IADJ)
N16783106: R3.1 U7.8(DEN)
N16797325: R17.1 U6.8(P4)
N16882731: RJ10.3 RJ11.3 U19.4(O)
N24600234: R10.1 R20.1 U20.2(SCLA)
N24600238: R9.1 R21.1 U20.3(SDAA)

Pads without a net: J1 6 8 10 12 14 16 53; NOREF#4 1; NOREF#6 1; NOREF#7 1; NOREF#12 1; NOREF#18 1; NOREF#21 1; NOREF#22 1; NOREF#23 1; P1 2 3; P3 14; U1 1; U3 1; U6 13 14 15 16 17 18 19 20; U7 1 5 6 11 12; U8 1; U9 49; U10 1 2 7 8 14 15 16 17 19 20 21 22 24; U19 1

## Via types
v1: diameter 0.508, hole 0.254, TOP to BOTTOM, 280 vias
v2: diameter 0.635, hole 0.305, TOP to BOTTOM, 25 vias

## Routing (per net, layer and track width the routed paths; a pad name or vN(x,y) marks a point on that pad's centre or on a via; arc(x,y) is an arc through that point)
GND: length 456.2
  TOP w0.254: R6.1 v1(51.31,28.32)
  TOP w0.305: 10.73,16.7 J1.61 ; J1.61 9.08,17.27 ; J1.61 10.73,17.84 ; 11.03,9.27 11.03,10.41 ; 11.03,9.27 11.03,8.13 ; 11.03,9.27 10.54,9.27 10.29,9.53 v1(10.29,10.29) ; 46.23,54.99 C1.2 ; C1.2 48.51,54.99 ; C1.2 47.37,54.23 ; C1.2 47.37,55.75 ; P3.MTG2 62.7,2.67 ; P3.MTG2 61.45,1.42 ; P3.MTG2 60.21,2.67 ; J1.35 v1(20.43,21.68) ; C15.2 46.17,24.64 ; C15.2 45.02,24.64 ; C15.2 45.59,25.21 ; 51.82,20 RJ4.3 ; RJ4.3 52.39,20.57 ; RJ4.3 v1(51.82,21.34) ; 57.78,53.28 C3.2 ; C3.2 57.21,53.85 ; C3.2 57.78,54.42 ; 22.74,4.8 U2.3 ; U2.3 23.23,5.39 ; U2.3 v1(23.23,3.95) ; 46.1,25.48 C16.2 47.12,26.18 ; 48.64,47.37 49.4,47.37 v1(49.53,47.5) ; 48.64,47.37 48.64,46.8 ; 48.64,47.37 48.64,47.94 ; U19.3 65.67,46.2 ; U19.3 66.14,45.62 ; U19.3 65.67,45.03 ; 50.04,34.92 C10.2 ; C10.2 51.56,34.92 ; C10.2 50.8,33.78 ; C8.2 52.58,40.26 ; C8.2 51.44,39.5 ; C8.2 50.29,40.26 ; C8.2 51.44,41.02 ; 3.94,7.91 U5.4 ; U5.4 4.51,9.44 ; U5.4 3.36,9.44 ; C32.2 55.88,19.3 v1(56.01,19.43) ; 60.14,54.51 P1.5 ; P1.5 64.66,54.51 ; P1.5 62.4,52.24 ; P1.5 62.4,56.77 ; 66.14,45.62 v1(66.42,45.34) ; 66.14,45.62 66.16,45.62 ; C7.2 48.9,41.02 ; C7.2 50.04,40.26 ; C7.2 47.75,40.26 ; C7.2 48.9,39.5 ; R4.2 48.51,33.02 v1(48.64,33.15) ; R4.2 47.75,33.59 ; R4.2 47.75,32.45 ; 49.91,54.23 C2.2 ; C2.2 49.91,55.75 ; C2.2 48.77,54.99 ; C2.2 51.05,54.99 ; RJ7.3 51.82,17.34 ; RJ7.3 51.82,16.19 ; RJ7.3 51.83,16.76 v1(52.58,17.51) ; RJ6.1 49.02,18.03 v1(48.9,17.91) ; v1(15.89,21.59) 15.89,20.39 J1.17 ; J1.64 29.27,17.27 ; J1.64 27.62,17.84 ; J1.64 27.62,16.7 ; RJ3.1 v1(54.1,24.13) ; P1.6 62.4,43.63 ; P1.6 62.4,39.1 ; P1.6 64.66,41.36 ; P1.6 60.14,41.36 ; C4.2 51.82,49.53 ; C4.2 51.05,50.67 ; C4.2 50.29,49.53 ; C4.2 51.05,48.39 ; 66.35,16.51 P3.MTG3 ; P3.MTG3 67.6,17.75 ; P3.MTG3 65.11,17.75 ; P3.MTG3 66.35,19 ; 63.37,33.59 63.37,32.45 ; P2.4 59.69,27.71 ; P2.4 60.74,26.65 ; P2.4 59.69,25.6 ; P2.4 58.64,26.65 ; v1(49.06,19.47) 49.22,19.3 RJ5.1 ; C38.1 63.69,46.48 ; C38.1 62.55,46.48 ; C38.1 63.12,45.91 ; 16,16.7 J1.62 16,17.84 ; 52.83,40.26 C9.2 ; C9.2 53.98,39.5 ; C9.2 53.98,41.02 ; C9.2 55.12,40.26 ; C35.2 57.78,21.08 v1(58.04,21.34) ; 52.2,27.75 R6.1 52.2,28.89 ; J1.22 v1(16.93,13.04) ; 66.35,0.81 P3.MTG4 ; P3.MTG4 65.11,2.06 ; P3.MTG4 66.35,3.3 ; P3.MTG4 67.6,2.06 ; 46.74,30.8 C12.2 ; C12.2 46.74,31.94 ; C12.2 v1(45.85,31.37) ; RJ8.3 v1(31.11,11.3) ; RJ8.3 29.78,11.3 ; RJ8.3 30.35,10.73 ; 20.3,4.22 U4.3 ; U4.3 v1(20.3,5.57) ; U4.3 19.82,4.8 ; 60.14,23.58 P2.6 ; P2.6 62.4,21.32 ; P2.6 64.66,23.58 ; P2.6 62.4,25.85 ; 53.66,21.97 C31.2 54.8,21.97 ; v1(26.15,5.59) U3.3 ; U3.3 26.15,4.22 ; U3.3 25.66,4.8 ; R8.2 v1(59.44,14.73) ; RJ2.1 v1(54.1,25.4) ; 59.69,43.38 P1.4 ; P1.4 58.64,44.43 ; P1.4 60.74,44.43 ; P1.4 59.69,45.49 ; C5.2 47.62,46.29 ; C5.2 47.62,45.15 ; C5.2 v1(46.74,45.72) ; P2.5 62.4,38.99 ; P2.5 64.66,36.73 ; P2.5 62.4,34.46 ; P2.5 60.14,36.73 ; R19.2 66.04,44.51 ; R19.2 66.04,43.37 ; R19.2 66.61,43.94 ; 56.9,26.1 RJ1.3 ; RJ1.3 56.9,27.24 ; RJ1.3 v1(57.66,26.67) ; 22.35,16.7 J1.63 22.35,17.84 ; 29.21,8.01 C28.2 28.19,7.32 ; J1.30 v1(18.93,12.96) ; 47.05,42.67 C6.2 ; C6.2 v1(47.62,41.91) ; C6.2 47.62,43.24 ; J1.18 v1(15.93,13.01) ; C13.2 v1(45.97,28.32) ; 50.67,23.1 C14.2 51.69,23.8 ; J1.36 v1(20.43,12.97)
  TOP w0.508: v1(47.75,55.93) 47.75,55.37 C1.2 46.99,55.37 v1(46.99,55.93) ; v1(51.99,49.91) 51.44,49.91 C4.2 51.44,49.15 v1(51.99,49.15) ; C31.2 v1(54.23,22.67) ; C24.2 v1(32.64,5.08) ; v1(49.53,55.93) 49.53,55.37 C2.2 50.29,55.37 v1(50.29,55.93) ; v1(41.53,4.45) 41.53,5 C27.2 42.29,5 v1(42.29,4.45) ; U5.4 v1(3.94,11.18) ; 63.37,33.02 v1(64.14,33.02) ; v1(46.74,26.42) 46.74,25.86 C16.2 47.5,25.86 v1(47.5,26.42) ; v1(51.74,35.31) 51.18,35.31 C10.2 51.18,34.54 v1(51.74,34.54) ; v1(49.28,41.2) 49.28,40.64 C7.2 48.51,40.64 v1(48.51,41.2) ; J1.61 v1(12.95,17.27) J1.62 v1(19.05,17.27) J1.63 v1(25.27,17.27) J1.64 ; v1(54.36,41.2) 54.36,40.64 C9.2 53.59,40.64 v1(53.59,41.2) ; v1(51.82,41.2) 51.82,40.64 C8.2 51.05,40.64 v1(51.05,41.2) ; v1(33.91,4.45) 33.91,5 C26.2 34.67,5 v1(34.67,4.45) ; C25.2 v1(40.13,5.08) ; v1(50.29,22.86) 50.29,23.42 C14.2 51.05,23.42 v1(51.05,22.86) ; C29.2 v1(35.61,7.32)
  L2-GND1 w0.508: P3.MTG3 67.75,17.75 ; P3.MTG3 66.35,19.15 ; P3.MTG3 66.35,16.36 ; P3.MTG3 64.95,17.75 ; P3.MTG1 61.45,18.54 ; P3.MTG1 62.85,17.14 ; P3.MTG1 61.45,15.75 ; P3.MTG1 60.06,17.14 ; P2.5 64.81,36.73 ; P2.5 59.99,36.73 ; P2.5 62.4,34.31 ; P1.5 64.81,54.51 ; P1.5 62.4,56.92 ; P1.5 59.99,54.51 ; P1.5 62.4,52.09 ; 58.48,26.65 P2.4 ; P2.4 60.9,26.65 ; P2.4 59.69,27.86 ; P2.4 59.69,25.45 ; P1.4 60.9,44.43 ; P1.4 58.48,44.43 ; P1.4 59.69,45.64 ; P1.4 59.69,43.23 ; 59.99,41.36 P1.6 ; P1.6 64.81,41.36 ; P1.6 62.4,43.78 ; P2.6 62.4,26 ; P2.6 62.4,21.17 ; P2.6 64.81,23.58 ; P2.6 59.99,23.58 ; 61.45,1.27 P3.MTG2 ; P3.MTG2 60.06,2.67 ; P3.MTG2 61.45,4.06 ; P3.MTG2 62.85,2.67 ; 64.95,2.06 P3.MTG4 ; P3.MTG4 66.35,3.45 ; P3.MTG4 67.75,2.06
  L5-GND2 w0.508: P1.4 59.69,45.64 ; P1.4 58.48,44.43 ; P1.4 60.9,44.43 ; P1.4 59.69,43.23 ; 58.48,26.65 P2.4 ; P2.4 59.69,25.45 ; P2.4 59.69,27.86 ; P2.4 60.9,26.65 ; 62.4,21.17 P2.6 ; P2.6 62.4,26 ; P2.6 64.81,23.58 ; P2.6 59.99,23.58 ; P1.6 64.81,41.36 ; P1.6 59.99,41.36 ; P1.6 62.4,43.78 ; P3.MTG4 66.35,3.45 ; P3.MTG4 64.95,2.06 ; P3.MTG4 67.75,2.06 ; P3.MTG1 62.85,17.14 ; P3.MTG1 61.45,15.75 ; P3.MTG1 60.06,17.14 ; P3.MTG1 61.45,18.54 ; P3.MTG3 67.75,17.75 ; P3.MTG3 64.95,17.75 ; P3.MTG3 66.35,19.15 ; P3.MTG3 66.35,16.36 ; P3.MTG2 62.85,2.67 ; P3.MTG2 61.45,1.27 ; P3.MTG2 60.06,2.67 ; P3.MTG2 61.45,4.06 ; P1.5 64.81,54.51 ; P1.5 62.4,56.92 ; P1.5 62.4,52.09 ; P1.5 59.99,54.51 ; 62.4,34.31 P2.5 ; P2.5 59.99,36.73 ; P2.5 64.81,36.73
  BOTTOM w0.203: U10.5 57.1,17.42 v1(57.11,17.4) ; U10.13 55.09,21.27 v1(55.07,21.29) ; U10.18 v1(57.1,21.38)
  BOTTOM w0.305: P3.MTG2 62.77,2.67 ; P3.MTG2 61.45,3.99 ; P3.MTG2 61.45,1.35 ; P3.MTG2 60.13,2.67 ; C40.2 v1(13.72,4.7) ; C40.2 14.29,3.94 ; C40.2 13.14,3.94 ; TP16.1 6.8,9.02 ; TP16.1 4.57,7.62 ; TP16.1 2.35,9.02 ; 58.4,3.19 U11.2 57.65,3.23 ; U7.4 v1(52.13,45.4) ; U8.13 46.16,31.05 v1(45.85,31.37) ; v1(42.8,9.91) 42.48,10.22 U9.17 ; P3.5 v1(62,7.16) ; U9.16 v1(45.85,13.14) 46.16,12.83 C37.2 ; U9.16 44.48,12.74 ; U9.16 43.33,13.14 ; 62.4,56.84 P1.5 64.74,54.51 ; 5.9,3.68 R15.2 7.05,3.68 ; C30.2 v1(26.67,3.94) ; C30.2 27.43,4.51 ; C30.2 28,3.94 ; P2.6 64.74,23.58 ; P2.6 60.06,23.58 ; P2.6 62.4,21.25 ; P2.6 62.4,25.92 ; P2.4 60.82,26.65 ; P2.4 59.69,25.52 ; P2.4 58.56,26.65 ; P2.4 59.69,27.79 ; P3.2 v1(62,5.66) ; v2(40.64,13.08) 40.98,12.74 U9.20 ; v1(46.74,45.72) 47.05,45.4 U7.13 ; 57.26,11.95 U17.2 56.51,11.99 ; 56.08,11.55 U16.2 56.12,12.3 ; 51.21,17.51 U1.3 ; U1.3 v1(52.58,17.51) ; U1.3 51.79,17.03 ; C36.2 v1(18.16,4.7) ; 56.08,9.79 U15.2 56.12,9.03 ; U9.17 42.48,12.29 ; U9.17 42.89,11.15 ; 45.78,53.34 TP15.1 ; TP15.1 48.01,51.94 ; TP15.1 50.23,53.34 ; P1.4 60.82,44.43 ; P1.4 59.69,43.3 ; P1.4 58.56,44.43 ; U9.26 37.99,12.33 v2(38.73,13.08) ; P3.MTG1 62.77,17.14 ; P3.MTG1 61.45,18.47 ; P3.MTG1 61.45,15.82 ; P3.MTG1 60.13,17.14 ; U9.64 42.48,23.77 ; U9.64 42.48,20.76 v2(42.55,20.7) ; U9.64 42.89,22.63 ; P3.MTG3 67.67,17.75 ; P3.MTG3 66.35,19.08 ; P3.MTG3 65.03,17.75 ; P3.MTG3 66.35,16.43 ; U9.48 34.14,20.64 ; U9.48 31.81,20.64 v1(31.62,20.83) ; U9.48 32.99,21.05 ; 34.36,13.64 U9.34 ; 7.17,2.67 C34.1 7.75,2.09 ; v1(61.98,13.21) 61.93,13.16 P3.17 ; 65.03,2.06 P3.MTG4 ; P3.MTG4 66.35,3.38 ; P3.MTG4 66.35,0.74 ; P3.MTG4 67.67,2.06 ; 56.51,15.19 U18.2 57.26,15.22 ; 10.07,2.22 U20.4 ; U20.4 9.64,3.36 ; U20.4 10.07,4.51 ; 34.58,11.15 U9.32 ; U9.32 34.99,10.01 ; U9.32 34.99,12.29 ; P3.8 v1(62,8.66) ; C33.2 v1(20.83,3.68) ; C39.2 v1(14.61,6.6) ; v2(38.73,20.7) 38.49,20.95 U9.56 ; P3.11 v1(62,10.16) ; U8.4 v1(51.24,31.05)
  BOTTOM w0.508: v1(3.94,11.18) 4.57,10.54 TP16.1 ; U17.2 v1(56.87,11.6) ; v1(56.39,6.03) U13.2 ; TP15.1 48.01,55.68 v1(47.75,55.93) ; C34.1 v1(8.51,2.67) ; v1(55.27,12.36) U16.2 ; v1(57.56,6.51) U12.2 ; v1(55.24,8.95) U15.2 ; v1(57.4,14.29) U18.2 ; U11.2 v1(58.49,4.06) ; R15.2 v1(6.48,4.95) ; v1(57.31,8.54) U14.2
  vias: v1(1.27,26.67) v1(1.27,1.27) v1(10.79,16.13) v1(16.13,26.8) v1(25.15,11.56) v1(28.32,22.35) v1(28.83,8.38) v1(29.46,11.81) v1(29.72,8.38) v1(32.77,22.99) v1(42.67,25.4) v1(43.43,23.11) v1(45.59,25.4) v1(46.99,8.64) v1(48.64,7.87) v1(49.66,14.1) v1(53.85,14.86) v1(53.85,12.19) v1(53.85,9.14) v1(54.99,5.97) v1(54.99,3.68) v1(56.77,53.85) v1(63.12,45.59) v1(67.06,43.94) v2(34.92,20.7) v2(34.92,18.8) v2(34.92,16.89) v2(34.92,14.99) v2(34.92,13.08) v2(36.83,20.7) v2(36.83,18.8) v2(36.83,16.89) v2(36.83,14.99) v2(36.83,13.08) v2(38.73,18.8) v2(38.73,16.89) v2(38.73,14.99) v2(40.64,20.7) v2(40.64,18.8) v2(40.64,16.89) v2(40.64,14.99) v2(42.55,18.8) v2(42.55,16.89) v2(42.55,14.99) v2(42.55,13.08)
VBUS2: length 11.6
  TOP w0.508: C11.1 61.72,33.02 61.09,33.66 P2.1
  BOTTOM w0.305: 53.7,31.69 U8.3 51.51,31.69 ; 59.69,32.57 P2.1 ; P2.1 58.61,33.66 ; P2.1 60.77,33.66 ; P2.1 59.69,34.74 ; 53.7,32.32 U8.2 51.51,32.32
VBUS_AUX: length 11.9
  TOP w0.508: C3.1 59.69,52.96 P1.1
  BOTTOM w0.305: 59.69,50.3 P1.1 ; P1.1 60.82,51.44 ; P1.1 59.69,52.57 ; P1.1 58.56,51.44 ; 54.64,46.67 U7.2 52.35,46.67 ; 54.64,46.04 U7.3 52.35,46.04
A3/DK3: length 16.9
  TOP w0.127: v1(53.59,26.04) 55.24,26.04 RJ1.2
  BOTTOM w0.127: U9.6 45.49,18.14 45.71,17.91 46.49,17.91 47.5,18.92 47.5,21.97 50.67,25.15 52.7,25.15 v1(53.59,26.04)
BSEL/SCL: length 47.5
  TOP w0.127: RJ7.2 50.8,16.31 v1(48.13,13.64) 48.13,12.57 45.97,10.41 45.97,5.46 43.37,2.86 v1(33.78,2.86) ; U4.2 v1(20.95,6.22)
  BOTTOM w0.127: v1(48.13,13.64) U9.15 ; v1(20.95,6.22) 21.46,6.73 32,6.73 33.27,5.46 33.27,3.37 v1(33.78,2.86)
CLT2/A1/DK2: length 16.5
  TOP w0.127: RJ2.2 55.24,24.77 v1(53.59,24.77)
  BOTTOM w0.127: v1(53.59,24.77) 50.8,24.77 47.88,21.84 47.88,18.8 46.61,17.53 45.59,17.53 45.48,17.64 U9.7
CON_LCD_PWR_DN: length 79.6
  TOP w0.127: RJ10.1 RJ11.1 v1(62.74,49.53) R2.2 ; J1.40 v1(21.43,12.86)
  L4-SIGNAL w0.133: v1(53.05,18.63) 47.97,18.63 43.69,14.35 33.02,14.35 32.64,14.73 30.23,14.73 27.81,12.32 22.04,12.32 21.5,12.86 v1(21.43,12.86)
  BOTTOM w0.127: U1.2 52.58,18.16 v1(53.05,18.63) 53.59,19.18 53.59,21.21 54.86,22.48 57.66,22.48 62.36,27.18 62.36,32.38 65.53,35.56 65.53,44.2 62.74,46.99 v1(62.74,49.53)
CONN_USB2_DM: length 3.5
  BOTTOM w0.122: P2.2 58.77,30.24 57.59,30.24 57.33,30.51 FL1.3
CONN_USB2_DP: length 3.4
  BOTTOM w0.122: FL1.2 57.33,29.69 57.59,29.96 58.88,29.96 P2.3
CT_HPD: length 97.9
  TOP w0.127: 14.93,9.27 14.93,7.69 13.08,5.84 11.3,5.84 10.16,4.7 10.16,2.16 11.43,0.89 56.64,0.89 59.82,4.06 63.88,4.06 66.67,6.86 66.67,14.61 59.44,21.84 56.77,21.84 53.72,18.8 v1(53.72,18.16) 53.72,18.16 53.72,17.4
  BOTTOM w0.127: v1(53.72,18.16) 53.98,18.41 53.98,18.92 54.28,19.23 U10.11
CTL1/A1/DK1: length 16.2
  TOP w0.127: v1(53.47,23.5) 55.24,23.5 RJ3.2
  BOTTOM w0.127: U9.8 46.86,17.14 48.26,18.54 48.26,21.72 50.04,23.5 v1(53.47,23.5)
DISP_SCL: length 35.6
  TOP w0.127: U5.6 v1(5.21,5.97) ; 20.32,2.8 U4.4 19.71,2.82 18.8,1.91 17.14,1.91 16.88,2.17 U6.22 16.88,5.96 v1(16.89,5.97) 19.43,8.5 J1.32
  BOTTOM w0.127: v1(16.89,5.97) 12.06,5.97 11.37,6.66 U20.7 11.37,8.95 10.92,9.4 9.14,9.4 5.71,5.97 v1(5.21,5.97)
DISP_SDA: length 41.2
  TOP w0.127: U5.5 v1(3.94,5.08) ; U2.4 23.23,2.05 v1(23.24,2.03) ; J1.34 19.93,7.86 v1(17.53,5.46) 17.53,5.21 17.53,5.2 U6.23
  BOTTOM w0.127: v1(3.94,5.08) 5.46,5.08 9.4,9.02 10.54,9.02 10.72,8.83 U20.6 10.72,6.55 11.81,5.46 v1(17.53,5.46) 17.53,2.54 18.03,2.03 v1(23.24,2.03)
DKEN: length 3.8
  TOP w0.127: v1(31.5,14.14) 31.5,13.46 30.35,12.32
  BOTTOM w0.127: U9.35 v1(31.5,14.14)
DSEL/SDA: length 45
  TOP w0.127: v1(32.13,2.92) 32.51,3.3 43.31,3.3 45.59,5.59 45.59,10.79 47.5,12.7 v1(47.5,14.14) 47.5,16 48.9,17.4 50.16,17.4 RJ6.2 ; U2.2 v1(23.88,6.22)
  BOTTOM w0.127: v1(23.88,6.22) 30.61,6.22 32.13,4.7 v1(32.13,2.92) ; v1(47.5,14.14) U9.14
EDGE/HTPLG: length 54.1
  TOP w0.127: RJ4.2 50.16,19.94 48.77,19.94 48.39,19.56 48.39,18.92 46.74,17.27 v1(46.74,16.64) 46.74,15.23 44.7,13.2 44.7,6.1 v1(43.31,4.7)
  BOTTOM w0.127: U9.9 46.6,16.64 46.61,16.64 v1(46.74,16.64) ; v1(43.31,4.7) 42.42,3.81 36.32,3.81 32.64,7.49 15.88,7.49 15.62,7.75 15.62,8.51 R17.2
GP1[2]_TOUCH_EVT: length 4.2
  TOP w0.127: RJ9.2 20.93,10.7 J1.38
HDMI_5V: length 18.8
  TOP w0.254: C31.1 v1(54.23,20.19)
  BOTTOM w0.203: v1(54.23,20.19) 54.23,19.94 54.54,19.63 U10.12
  BOTTOM w0.254: P3.18 59.36,13.66 58.67,14.35 58.67,15.37 59.44,16.13 59.44,17.65 60.45,18.67 60.45,20.19 58.67,21.97 54.99,21.97 54.23,21.21 v1(54.23,20.19)
HDMI_CEC: length 12
  TOP w0.127: R11.1 62.21,10.79 v1(61.85,11.16)
  BOTTOM w0.127: U10.6 56.7,17.71 56.64,17.65 56.64,16.76 58.17,15.24 58.17,13.46 58.93,12.7 58.93,11.56 59.32,11.16 P3.13 v1(61.85,11.16)
HDMI_CK+: length 8.6
  BOTTOM w0.112: FL5.2 54.97,13.18 55.19,13.41 55.8,13.41 U17.1 56.45,13.34 56.9,13.34 57.66,12.57 57.66,10.92 58.6,9.98 59.03,9.98 59.35,9.66 P3.10
HDMI_CK-: length 8.7
  BOTTOM w0.112: FL5.3 54.97,14 55.19,13.77 55.8,13.77 U18.1 56.6,13.69 57.04,13.69 58.01,12.72 58.01,11.07 58.75,10.34 59.03,10.34 59.35,10.66 P3.12
HDMI_D0+: length 8.3
  BOTTOM w0.112: P3.7 59.35,8.16 59.03,8.48 58.45,8.48 56.44,10.49 55.38,10.49 U15.1 54.66,10.49 54.05,10.49 53.82,10.26 FL4.2
HDMI_D0-: length 8.3
  BOTTOM w0.112: P3.9 59.35,9.16 59.03,8.84 58.6,8.84 56.59,10.85 55.38,10.85 U16.1 54.66,10.85 54.05,10.85 53.82,11.07 FL4.3
HDMI_D1+: length 6.5
  BOTTOM w0.112: P3.4 59.35,6.66 59.03,6.98 58.3,6.98 57.71,7.57 56.53,7.57 U13.1 55.8,7.57 55.19,7.57 54.97,7.34 FL3.2
HDMI_D1-: length 6.5
  BOTTOM w0.112: P3.6 59.35,7.66 59.03,7.34 58.45,7.34 57.86,7.92 56.53,7.92 U14.1 55.8,7.92 55.19,7.92 54.97,8.15 FL3.3
HDMI_D2+: length 5.5
  BOTTOM w0.112: P3.1 59.35,5.16 59.03,5.48 58.81,5.48 57.98,4.65 57.67,4.65 U11.1 56.95,4.65 56.34,4.65 56.11,4.42 FL2.2
HDMI_D2-: length 5.5
  BOTTOM w0.112: P3.3 59.35,6.16 59.03,5.83 58.67,5.83 57.84,5 57.67,5 U12.1 56.95,5 56.34,5 56.11,5.23 FL2.3
HDMI_DPD: length 11.7
  TOP w0.127: R7.1 62.1,14.22 v1(61.98,14.1) R8.1 60.58,14.61 60.2,14.61 59.56,15.24 58.42,15.24 56.77,16.89 v1(55.37,16.89)
  BOTTOM w0.127: v1(61.98,14.1) 61.91,14.16 P3.19 ; v1(55.37,16.89) 55.49,17.01 U10.9
HDMI_SCL: length 4.9
  TOP w0.127: v1(64.52,11.94) R20.2
  BOTTOM w0.127: P3.15 64.29,12.16 v1(64.52,11.94)
HDMI_SDA: length 5
  TOP w0.127: R21.2 v1(64.52,13.08)
  BOTTOM w0.127: v1(64.52,13.08) 64.1,12.66 P3.16
HPD_A: length 74.6
  TOP w0.127: v1(58.29,16.26) 58.93,15.62 59.69,15.62 60.33,14.99 v1(64.52,14.99) ; v1(62.99,6.6) 59.18,6.6 58.8,6.99 48.01,6.99 43.43,2.41 29.34,2.41 28.07,3.68 28.07,5.59 27.69,5.97 v1(27.69,8.13) ; RJ9.1 v1(21.46,8.38) ; 16.23,9.27 v1(16.23,8)
  BOTTOM w0.127: U10.3 57.9,17.79 58.29,17.4 v1(58.29,16.26) ; v1(62.99,6.6) 65.28,8.89 65.28,14.22 v1(64.52,14.99) ; v1(16.23,8) 21.08,8 v1(21.46,8.38) 21.72,8.13 v1(27.69,8.13)
ISEL/RSTN: length 44.1
  TOP w0.127: v1(27.05,5.59) 26.8,5.33 U3.2 ; RJ5.2 50.16,18.67 48.9,18.67 48.01,17.78 48.01,17.14 47.12,16.26 47.12,14.86 v1(46.86,14.61) 46.86,12.83 45.21,11.18 45.21,5.84 43.05,3.68 30.35,3.68 v1(29.65,2.98)
  BOTTOM w0.127: C37.1 48.13,12.83 48.64,13.34 48.64,13.84 47.88,14.61 v1(46.86,14.61) 46.83,14.64 U9.13 ; v1(29.65,2.98) v1(27.05,5.59)
ISELN: length 7.7
  TOP w0.127: U4.1 v1(21.61,5.7) ; U3.4 25.63,2.82 25.09,3.36 25.09,4.12 24.53,4.68 U2.1 v1(24.53,5.7)
  BOTTOM w0.127: v1(24.53,5.7) v1(21.61,5.7)
LCD_B0: length 23.8
  TOP w0.127: v1(41.53,26.04) 39.12,23.62 26.42,23.62 24.43,21.63 J1.51
  BOTTOM w0.127: U9.63 41.98,24.69 41.53,25.15 v1(41.53,26.04)
LCD_B1: length 23.9
  TOP w0.127: J1.49 23.93,21.77 27.05,24.89 39.5,24.89 v1(40.77,26.16)
  BOTTOM w0.127: v1(40.77,26.16) 40.77,25.27 41.48,24.56 U9.62
LCD_B2: length 23.8
  TOP w0.127: v1(40.01,26.16) 39.12,25.27 26.8,25.27 23.43,21.9 J1.47
  BOTTOM w0.127: v1(40.01,26.16) 40.01,25.53 40.98,24.55 U9.61
LCD_B3: length 23.7
  TOP w0.127: v1(39.12,26.16) 38.61,25.65 26.54,25.65 22.93,22.04 J1.45
  BOTTOM w0.127: U9.60 40.48,24.41 39.12,25.78 v1(39.12,26.16)
LCD_B4: length 23.7
  TOP w0.127: J1.43 22.43,22.17 26.67,26.42 37.97,26.42 v1(38.23,26.16)
  BOTTOM w0.127: v1(38.23,26.16) 39.98,24.4 U9.59
LCD_B5: length 23.8
  TOP w0.127: v1(24.64,25.4) 24,24.77 24,24.38 21.93,22.31 J1.41
  BOTTOM w0.127: U9.58 39.48,24.1 37.29,26.29 28.57,26.29 27.69,25.4 v1(24.64,25.4)
LCD_B6: length 23.5
  TOP w0.127: J1.39 21.43,22.57 23.24,24.38 v1(23.24,25.27)
  BOTTOM w0.127: U9.55 37.99,23.74 37.85,23.88 37.85,24.77 36.7,25.91 28.83,25.91 27.81,24.89 23.62,24.89 v1(23.24,25.27)
LCD_B7: length 23.4
  TOP w0.127: v1(22.48,25.15) 22.48,24.38 20.93,22.83 J1.37
  BOTTOM w0.127: U9.54 37.49,24.49 36.45,25.53 29.08,25.53 28.07,24.51 23.11,24.51 v1(22.48,25.15)
LCD_DE: length 34
  TOP w0.127: J1.28 18.43,15.06 v1(19.43,16.07)
  L4-SIGNAL w0.133: TP5.1 45.34,20.95 44.2,19.81 44.2,18.92 43.43,18.16 30.86,18.16 28.77,16.07 v1(19.43,16.07)
  BOTTOM w0.127: U9.2 45.54,20.14 TP5.1
LCD_G0: length 23.5
  TOP w0.127: v1(21.72,25.02) 21.72,24.38 20.45,23.11 20.45,22.61 19.93,22.09 J1.33
  BOTTOM w0.127: v1(21.72,25.02) 22.61,24.13 28.32,24.13 29.34,25.15 36.2,25.15 36.99,24.36 U9.53
LCD_G1: length 23.5
  TOP w0.127: J1.31 19.43,22.35 19.94,22.86 19.94,23.5 20.83,24.38 v1(20.83,24.89)
  BOTTOM w0.127: U9.52 36.49,24.22 35.94,24.77 29.59,24.77 28.57,23.75 21.97,23.75 v1(20.83,24.89)
LCD_G2: length 23.6
  TOP w0.127: J1.29 18.93,22.48 19.43,22.99 19.43,23.75 19.94,24.26 v1(19.94,24.89)
  BOTTOM w0.127: U9.51 35.99,23.96 35.56,24.38 29.97,24.38 28.96,23.37 21.46,23.37 v1(19.94,24.89)
LCD_G3: length 23.4
  TOP w0.127: v1(19.18,24.77) 18.92,24.51 18.92,23.11 18.43,22.62 J1.27
  BOTTOM w0.127: U9.50 35.49,23.7 35.18,24 30.35,24 29.34,22.99 20.95,22.99 v1(19.18,24.77)
LCD_G4: length 23.5
  TOP w0.127: J1.25 17.93,22.75 18.41,23.24 v1(18.41,24.26)
  BOTTOM w0.127: v1(18.41,24.26) 18.41,23.37 17.93,22.88 17.93,21.32 18.41,20.83 26.67,20.83 27.56,21.72 29.84,21.72 31.42,20.14 U9.47
LCD_G5: length 23.3
  TOP w0.127: v1(17.65,23.88) 17.65,23.24 17.43,23.02 J1.23
  BOTTOM w0.127: U9.46 31.41,19.64 29.72,21.34 27.69,21.34 26.8,20.45 18.16,20.45 17.43,21.18 17.43,23.14 17.65,23.37 v1(17.65,23.88)
LCD_G6: length 23.3
  TOP w0.127: v1(16.93,23.59) J1.21
  BOTTOM w0.127: U9.45 31.43,19.14 29.61,20.95 27.81,20.95 26.92,20.07 18.03,20.07 16.93,21.17 v1(16.93,23.59)
LCD_G7: length 23.5
  TOP w0.127: v1(16.26,23.24) 16.26,22.1 16.43,21.93 J1.19
  BOTTOM w0.127: U9.44 31.4,18.64 29.46,20.57 27.94,20.57 27.05,19.68 17.91,19.68 16.43,21.16 16.43,22.31 16.26,22.48 v1(16.26,23.24)
LCD_HS: length 34.5
  TOP w0.127: v1(18.16,15.62) 17.93,15.39 J1.26
  L4-SIGNAL w0.133: v1(18.16,15.62) 28.96,15.62 30.99,17.65 44.2,17.65 45.72,19.18 46.35,19.18 TP4.1
  BOTTOM w0.127: TP4.1 46.32,19.14 U9.4
LCD_PCLK: length 33.9
  TOP w0.127: J1.20 v1(16.43,15.88)
  L4-SIGNAL w0.133: v1(16.43,15.88) 17.19,16.64 28.45,16.64 34.67,22.86 35.51,22.86 35.7,22.66 35.7,21.79 35.9,21.59 36.17,21.59 36.37,21.79 36.37,22.66 36.56,22.86 36.84,22.86 37.03,22.66 37.03,21.79 37.23,21.59 37.85,21.59 38.48,22.23 TP2.1
  BOTTOM w0.127: TP2.1 38.98,23.75 U9.57
LCD_R0: length 23.3
  TOP w0.127: J1.15 v1(15.43,22.99)
  BOTTOM w0.127: v1(15.43,22.99) 15.43,21.28 17.4,19.3 26.42,19.3 27.69,18.03 31.62,18.03 31.73,18.14 U9.43
LCD_R1: length 23.4
  TOP w0.127: J1.13 v1(14.93,21.59)
  BOTTOM w0.127: v1(14.93,21.59) 14.93,21.27 17.27,18.92 23.63,18.92 23.82,18.74 23.82,18.35 24,18.16 24.27,18.16 24.45,18.35 24.45,18.74 24.64,18.92 24.89,18.92 25.28,18.53 25.67,18.53 25.98,18.84 26.24,18.84 26.43,18.66 26.43,18.39 26.12,18.08 26.12,17.82 26.3,17.64 U9.42
LCD_R2: length 23.4
  TOP w0.127: J1.11 v1(14.43,22.35)
  BOTTOM w0.127: U9.41 26.17,17.14 25.53,17.78 23.5,17.78 22.73,18.54 17.14,18.54 14.43,21.26 v1(14.43,22.35)
LCD_R3: length 23.4
  TOP w0.127: v1(13.93,21.59) J1.9
  BOTTOM w0.127: U9.40 22.98,16.64 22.8,16.82 22.8,17.08 22.98,17.27 22.98,17.53 22.8,17.71 22.53,17.71 22.35,17.53 22.09,17.53 21.46,18.16 16.89,18.16 13.93,21.12 v1(13.93,21.59)
LCD_R4: length 23.5
  TOP w0.127: v1(15.62,18.22) 15.56,18.22 14.48,19.3 13.59,19.3 13.43,19.46 J1.7
  BOTTOM w0.127: v1(15.62,18.22) 16.07,17.78 16.46,17.78 16.65,17.59 16.65,17.33 16.84,17.14 17.1,17.14 17.28,17.33 17.28,17.59 17.47,17.78 20.32,17.78 21.07,17.03 21.33,17.03 21.51,17.22 21.77,17.22 21.96,17.03 21.96,16.77 21.78,16.58 21.78,16.32 21.96,16.14 U9.39
LCD_R5: length 23.4
  TOP w0.127: v1(14.73,18.16) 13.94,18.95 13.44,18.95 12.93,19.46 J1.5
  BOTTOM w0.127: v1(14.73,18.16) 16.18,16.72 19.73,16.72 19.92,16.53 20.18,16.53 20.36,16.72 20.62,16.72 20.81,16.53 20.81,16.27 20.63,16.08 20.63,15.82 20.81,15.64 U9.38
LCD_R6: length 23.3
  TOP w0.127: J1.3 12.43,19.32 13.08,18.67 13.46,18.67 v1(13.97,18.16)
  BOTTOM w0.127: v1(13.97,18.16) 15.75,16.38 18.41,16.38 19.66,15.14 U9.37
LCD_R7: length 24
  TOP w0.127: v1(13.08,18.16) 11.93,19.31 J1.1
  BOTTOM w0.127: U9.36 16.6,14.64 v1(13.08,18.16)
LCD_VS: length 33.8
  TOP w0.127: J1.24 v1(17.43,15.37)
  L4-SIGNAL w0.133: v1(17.43,15.37) 17.68,15.11 29.08,15.11 31.11,17.14 33.66,17.14 34.54,16.26 42.93,16.26 43.81,17.14 44.7,17.14 TP3.1
  BOTTOM w0.127: U9.5 46,18.64 TP3.1
LS_OE: length 83.8
  TOP w0.127: v1(45.34,2.03) 46.04,1.33 56.58,1.33 56.58,1.33 59.69,4.45 63.63,4.45 66.17,6.99 66.17,14.1 64.77,15.49 60.58,15.49 59.82,16.26 59.18,16.26 58.39,17.04 v1(57.77,17.04) 57.78,17.06 R18.2 ; v1(10.07,6.39) 12.99,6.39 v1(14.48,7.87) 14.28,8.07 14.28,9.27
  BOTTOM w0.127: U20.5 v1(10.07,6.39) ; U10.4 57.5,17.69 57.77,17.42 v1(57.77,17.04) ; v1(45.34,2.03) 26.92,2.03 24.13,4.83 19.56,4.83 17.78,6.6 15.75,6.6 v1(14.48,7.87)
Net_3: length 0.6
  BOTTOM w0.127: 58.7,18.47 v1(59.31,18.47)
Net_4: length 1.3
  BOTTOM w0.127: v1(58.8,17.4) 58.3,17.9 58.3,18.47
Net_128: length 0.9
  BOTTOM w0.127: 58.88,19.23 v1(59.82,19.23)
PCF8575_OUT5: length 8.9
  TOP w0.127: TP9.1 9.14,11.81 12.06,11.81 12.98,10.9 12.98,9.27
PCF8575_OUT6: length 10
  TOP w0.127: TP8.1 6.22,12.83 7.62,12.83 9.02,11.43 11.56,11.43 12.33,10.66 12.33,9.27
PCF8575_OUT7: length 11.2
  TOP w0.127: TP7.1 4.83,12.32 7.49,12.32 8.76,11.05 11.18,11.05 11.68,10.55 11.68,9.27
PDN: length 5.9
  BOTTOM w0.127: U1.4 49.26,17.51 49.02,17.27 48.13,17.27 47,16.14 U9.10
TS_LCD_GPIO1: length 9.4
  TOP w0.127: J1.48 23.43,11.63 24.51,10.54 28.19,10.54 TP13.1
TS_LCD_GPIO2: length 8
  TOP w0.127: J1.46 22.93,11.62 24.38,10.16 26.67,10.16 TP12.1
TS_LCD_GPIO3: length 6.6
  TOP w0.127: J1.44 22.43,11.61 24.64,9.4 TP11.1
TS_LCD_GPIO4: length 14
  TOP w0.127: 18.18,9.27 v1(18.18,10.67) ; J1.42 21.93,12.15 21.46,11.68 RJ9.3 21.84,11.18 TP10.1
  BOTTOM w0.127: TP10.1 20.95,9.4 20.57,9.78 R14.2 18.18,9.8 v1(18.18,10.67)
TX0+: length 17.2
  BOTTOM w0.112: U9.25 38.49,10.07 38.56,10 38.56,9.2 40.11,7.65 47.27,7.65 50.11,10.49 51.03,10.49 51.26,10.26 FL4.1
TX0-: length 16.6
  BOTTOM w0.112: FL4.4 51.26,11.07 51.03,10.85 49.97,10.85 47.12,8 40.26,8 38.91,9.35 38.91,10 38.98,10.07 U9.24
TX1+: length 19.4
  BOTTOM w0.112: FL3.1 52.4,7.34 52.17,7.57 50.37,7.57 49.4,6.6 39.76,6.6 37.06,9.3 37.06,10 36.99,10.07 U9.28
TX1-: length 18.9
  BOTTOM w0.112: U9.27 37.49,10.07 37.41,10 37.41,9.45 39.9,6.96 49.26,6.96 50.22,7.92 52.17,7.92 52.4,8.15 FL3.4
TX2+: length 22.5
  BOTTOM w0.112: U9.31 35.49,10.07 35.56,10 35.56,9.28 39.22,5.61 51.8,5.61 52.76,4.65 53.32,4.65 53.55,4.42 FL2.1
TX2-: length 21.9
  BOTTOM w0.112: FL2.4 53.55,5.23 53.32,5 52.91,5 51.94,5.97 39.37,5.97 35.91,9.43 35.91,10 35.99,10.07 U9.30
TXC+: length 17.2
  BOTTOM w0.112: U9.22 39.98,10.07 40.06,10 40.06,9.22 40.62,8.66 46.13,8.66 50.93,13.46 52.12,13.46 52.4,13.18 FL5.1
TXC-: length 16.6
  BOTTOM w0.112: FL5.4 52.4,14 52.22,13.82 50.78,13.82 45.98,9.02 40.77,9.02 40.41,9.37 40.41,10 40.48,10.07 U9.21
USB2_DRV_VBUS: length 66.6
  TOP w0.127: U19.2 R19.1 v1(64.26,43.94) ; J1.50 v1(23.93,12.88)
  L4-SIGNAL w0.133: v1(52.96,21.46) 51.44,19.94 48.64,19.94 44.45,15.75 30.48,15.75 28.32,13.59 24.64,13.59 v1(23.93,12.88)
  BOTTOM w0.127: v1(64.26,43.94) 65.15,43.05 65.15,35.69 61.98,32.51 61.98,27.29 57.93,23.24 53.98,23.24 52.96,22.23 v1(52.96,21.46)
USB2_VBUS_OCN: length 70.4
  TOP w0.127: v1(15.62,10.67) 15.62,9.31 15.58,9.27 ; TP1.1 45.34,37.08 45.34,30.61 45.85,30.1 v1(45.85,29.21) 45.97,29.34 R5.2
  BOTTOM w0.127: U7.10 46.8,43.5 46.35,43.05 TP1.1 ; U8.10 45.91,29.15 v1(45.85,29.21) 45.47,28.83 45.47,27.43 45.09,27.05 17.53,27.05 11.94,21.46 11.94,16.38 14.99,13.34 14.99,11.3 v1(15.62,10.67)
USB2_VD+: length 2.6
  BOTTOM w0.122: FL1.1 54.43,29.69 54.17,29.96 53.82,29.96 53.64,29.78 U8.6
USB2_VD-: length 2.6
  BOTTOM w0.122: U8.5 53.64,30.42 53.82,30.24 54.17,30.24 54.43,30.51 FL1.4
USB_DM_DN2: length 40.8
  TOP w0.122: J1.52 24.43,13.3 24.54,13.19 24.54,12.55 24.89,12.19 27.07,12.19 33.02,18.15 33.02,21.72 33.66,22.35 41.42,22.35 46.34,27.28 49.01,27.28 49.92,28.19 49.92,28.79 v1(50.21,29.07)
  BOTTOM w0.122: v1(50.21,29.07) 49.92,29.35 49.92,29.96 49.64,30.24 48.44,30.24 48.26,30.42 U8.12
USB_DP_DN2: length 39.4
  TOP w0.122: J1.54 24.93,13.3 24.82,13.19 24.82,12.66 25.01,12.47 26.95,12.47 32.74,18.26 32.74,21.83 33.54,22.63 41.3,22.63 46.23,27.56 48.9,27.56 49.64,28.31 49.64,28.79 v1(49.36,29.07)
  BOTTOM w0.122: v1(49.36,29.07) 49.64,29.35 49.64,29.84 49.53,29.96 48.44,29.96 48.26,29.78 U8.11
USBP1_PWR_VENN: length 17.2
  TOP w0.127: RJ10.2 v1(64.64,51.82)
  BOTTOM w0.127: v1(64.64,51.82) 63.63,51.82 61.47,49.66 61.47,46.48 60.58,45.59 56.64,45.59 54.55,43.5 U7.7
USBP2_PWR_VENN: length 33
  TOP w0.127: RJ11.2 v1(64.64,50.29)
  BOTTOM w0.127: v1(64.64,50.29) 62.74,50.29 61.98,49.53 61.98,44.58 56.64,39.24 52.32,39.24 50.42,37.34 50.42,30.23 51.5,29.15 U8.7
V_DVDD: length 8
  TOP w0.305: C18.1 44.88,19.64 v1(45.8,19.64) ; C19.1 44.8,15.14 v1(45.75,15.14) ; v1(32.77,12.45) C20.1 ; v1(44.7,21.46) C17.1
  BOTTOM w0.305: v1(32.77,12.45) 32.99,12.67 U9.33 ; U9.3 v1(45.8,19.64) ; v1(44.7,21.46) 44.48,21.23 U9.1 ; U9.12 v1(45.75,15.14)
V_PVDD: length 1.3
  BOTTOM w0.305: U9.18 v1(41.98,9.83)
V_TVDD: length 2.7
  BOTTOM w0.305: v1(39.5,9.78) 39.5,11.14 U9.23 ; U9.29 v1(36.49,9.78)
VIO_1V8: length 3.5
  TOP w0.305: J1.4 v1(12.43,12.95) ; v1(11.56,12.95) 11.93,13.33 J1.2
  BOTTOM w0.305: v1(11.56,12.95) v1(12.43,12.95)
VIO_3V3: length 48.6
  TOP w0.254: R3.2 v1(52.2,42.67)
  TOP w0.305: U3.5 v1(28.19,2.82) ; J1.56 v1(25.43,12.98) ; v1(57.66,24.13) RJ3.3 RJ2.3 ; RJ7.1 v1(49.02,16.76) ; 16.88,9.27 16.88,10.4 v1(17.14,10.67) 17.53,10.28 17.53,9.27 ; J1.58 25.93,13.32 v1(26.29,12.95) ; RJ1.1 v1(54.1,26.67) ; R11.2 v1(64.52,10.79) ; U6.24 18.92,3.43 v1(19.05,3.3) ; v1(64.37,48.5) U19.5 63.22,47.6 C38.2 ; U4.5 21.63,2.79 v1(22.35,2.79) ; v1(49.53,42.67) 48.64,42.67 ; v1(48.51,28.45) 48.39,28.32 C13.1 ; U6.21 v1(16.23,2.06) ; RJ8.1 v1(30.35,14.1) ; RJ4.1 v1(49.02,20.57) ; R2.1 v1(61.98,51.31) ; RJ6.3 RJ5.3 v1(52.58,19.3) ; R5.1 v1(48.51,29.34) ; U2.5 v1(24.53,3.54) ; J1.60 v1(27.01,14.19)
  TOP w0.508: v1(54.48,16.4) 53.75,16.4 R13.1 ; U5.3 v1(5.21,11.18) ; U5.2 v1(6.48,11.18) ; v1(59.66,19.96) 59.31,20.32 C35.1 ; R18.1 v1(57.28,19.43) ; U5.8 v1(7.75,4.95) ; U5.1 v1(7.75,11.18)
  BOTTOM w0.203: v1(59.66,19.96) 59.33,19.63 U10.23
  BOTTOM w0.305: v1(49.53,42.67) 49.34,42.86 U7.9 ; v1(52.58,19.3) 52.2,19.68 50.68,19.68 U1.5 ; v1(28.19,2.82) 28.09,2.92 C30.1 ; R12.1 v1(51.56,15.49) ; v1(22.35,2.79) 22.23,2.67 C33.1 ; U20.8 12.64,7.81 v1(12.83,7.62) C39.1 ; v1(19.05,3.3) 18.67,2.92 C36.1 ; R14.1 v1(18.92,8.76) ; U8.9 48.45,28.51 v1(48.51,28.45)
  BOTTOM w0.508: v1(7.75,4.95) C34.2
  vias: v1(28.96,4.45) v1(29.72,4.45) v1(31.11,4.7) v1(36.45,4.45) v1(37.21,4.45) v1(38.73,4.7) v1(48.9,26.42) v1(50.29,26.67) v1(51.05,26.67)
VSYS_5V0: length 40.9
  TOP w0.305: J1.59 26.43,21.35 v1(26.67,21.59) ; J1.57 v1(25.93,21.72) ; R10.2 R9.2 59.31,12.95 v1(59.05,13.21) ; 48.64,45.72 49.4,45.72 v1(49.53,45.85) ; C12.1 48.51,31.37 v1(48.64,31.5) ; J1.55 25.43,21.31 v1(25.15,21.59) ; R7.2 v1(64.52,14.22)
  TOP w0.508: v1(47.07,49.15) 47.62,49.15 C4.1 47.62,49.91 v1(47.07,49.91) ; v1(49.53,51) 49.53,51.56 C2.1 50.29,51.56 v1(50.29,51) ; v1(48.51,36.27) 48.51,36.83 C7.1 49.28,36.83 v1(49.28,36.27) ; v1(46.99,51) 46.99,51.56 C1.1 47.75,51.56 v1(47.75,51) ; v1(46.81,35.31) 47.37,35.31 C10.1 47.37,34.54 v1(46.81,34.54) ; v1(54.86,17.48) 55.24,17.86 C32.1 ; v1(53.59,36.27) 53.59,36.83 C9.1 54.36,36.83 v1(54.36,36.27) ; v1(51.82,36.27) 51.82,36.83 C8.1 51.05,36.83 v1(51.05,36.27)
  L3-SIGNAL w0.508: v1(59.05,13.21) 59.56,13.21 61.34,14.99 62.61,14.99 63.37,14.22 v1(64.52,14.22)
  BOTTOM w0.203: U10.10 55.09,17.71 v1(54.86,17.48)
  BOTTOM w0.305: v1(48.64,31.5) 48.45,31.69 U8.14 ; v1(49.53,45.85) 49.34,46.04 U7.14 ; U8.15 v1(48.64,32.32) ; U20.1 v1(12.02,2.03) ; C40.1 v1(13.72,2.03) ; U7.15 v1(49.53,46.67)
N22084: length 2.5
  TOP w0.127: v1(41.27,9.53) 41.27,9.78 R16.2
  BOTTOM w0.127: U9.19 41.48,10.12 41.27,9.91 v1(41.27,9.53)
N30894: length 5.4
  BOTTOM w0.127: R12.2 TP6.1 47.75,15.49 47.6,15.64 U9.11
N46927: length 3.1
  TOP w0.127: v1(6.48,1.4) U5.7
  BOTTOM w0.127: R15.1 v1(6.48,1.4)
N16782581: length 2.3
  TOP w0.127: v1(45.85,33.02) R4.1
  BOTTOM w0.127: U8.16 45.91,32.96 v1(45.85,33.02)
N16782836: length 2.4
  TOP w0.127: v1(54.04,28.32) R6.2
  BOTTOM w0.127: v1(54.04,28.32) 53.98,28.32 53.98,28.38 53.85,28.51 U8.8
N16782935: length 2.3
  TOP w0.127: v1(46.74,47.37) R1.1
  BOTTOM w0.127: U7.16 46.8,47.31 v1(46.74,47.37)
N16783106: length 2.4
  TOP w0.127: v1(54.93,42.67) R3.1
  BOTTOM w0.127: v1(54.93,42.67) 54.86,42.67 54.86,42.74 54.74,42.86 U7.8
N16797325: length 2.3
  TOP w0.127: 13.63,9.27 13.59,9.31 v1(13.59,10.67)
  BOTTOM w0.127: R17.1 v1(13.59,10.67)
